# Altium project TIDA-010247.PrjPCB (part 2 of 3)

## Sheet Aux power.SchDoc
size 431 x 279 mm; Date: Not shown in title block; ApprovedBy: Not shown in title block; CheckedBy: Not shown in title block; Author: Not shown in title block; CompanyName: Not shown in title block; Engineer: Not shown in title block; Organization: Not shown in title block; Address1: Not shown in title block; Address2: Not shown in title block; Address3: Not shown in title block; Address4: Not shown in title block; DocumentNumber: 5; Revision: Use project parameter SCH_Rev; SheetNumber: 5; SheetTotal: 7; PageSetup: Record=PageOptions¦CenterHorizontal=True¦CenterVertical=True¦PrintScale=1.00¦XCorrection=1.00¦YCorrection=1.00¦PrintKind=0¦BorderSize=5000000¦LeftOffset=0¦BottomOffset=0¦Orientation=2¦PaperLength=1000¦PaperWidth=1000¦Scale=100¦PaperSource=15¦PrintQuality=600¦MediaType=1¦DitherType=10¦PaperKind=Letter¦PrintScaleMode=1
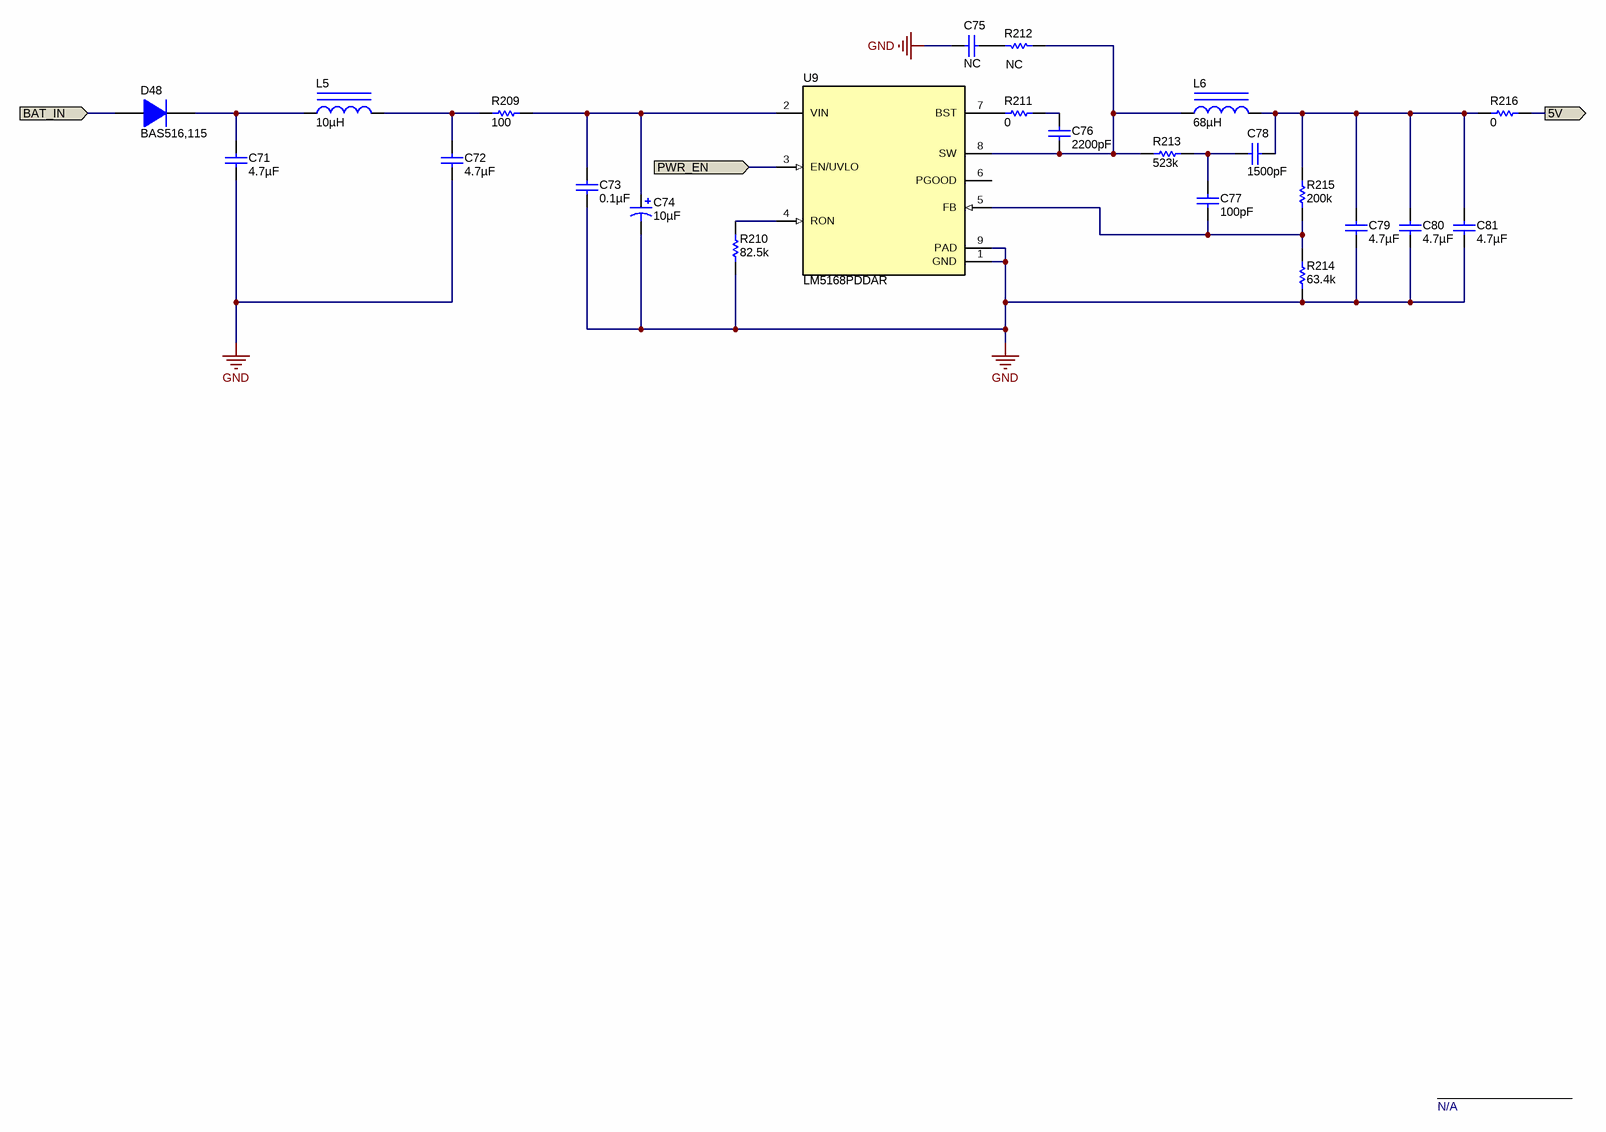
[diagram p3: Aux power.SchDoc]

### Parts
C71  ValueDisplayed: 4.7µF  [1210]  (hidden comment: C3225X7S2A475K200AE)
C72  ValueDisplayed: 4.7µF  [1210]  (hidden comment: C3225X7S2A475K200AE)
C73  ValueDisplayed: 0.1µF  [0603]  (hidden comment: GRM188R72A104KA35D)
C74  ValueDisplayed: 10µF  [UUX_800x620]  (hidden comment: UUX2A100MNL1GS)
C75  ValueDisplayed: NC  [0603]  (hidden comment: GRM1885C1H560JA01D)
C76  ValueDisplayed: 2200pF  [0402]  (hidden comment: GRM155R71H222KA01D)
C77  ValueDisplayed: 100pF  [0603]  (hidden comment: GRM1885C2A101JA01D)
C78  ValueDisplayed: 1500pF  [0402]  (hidden comment: GRM155R71H152KA01D)
C79  ValueDisplayed: 4.7µF  [0805_HV]  (hidden comment: GRM21BR71C475KA73L)
C80  ValueDisplayed: 4.7µF  [0805_HV]  (hidden comment: GRM21BR71C475KA73L)
C81  ValueDisplayed: 4.7µF  [0805_HV]  (hidden comment: GRM21BR71C475KA73L)
D48  BAS516,115  [SOD-523]
L5  ValueDisplayed: 10µH  [WE-MAPI_3015]  (hidden comment: 74438335010)
L6  ValueDisplayed: 68µH  [WE-PD_7345]  (hidden comment: 744777168)
R209  ValueDisplayed: 100  [0603]  (hidden comment: CRCW0603100RFKEA)
R210  ValueDisplayed: 82.5k  [0603]  (hidden comment: CRCW060382K5FKEA)
R211  ValueDisplayed: 0  [0402]  (hidden comment: CRCW04020000Z0ED)
R212  ValueDisplayed: NC  [0603]  (hidden comment: RC0603FR-07499KL)
R213  ValueDisplayed: 523k  [0402]  (hidden comment: RC0402FR-07523KL)
R214  ValueDisplayed: 63.4k  [0603]  (hidden comment: CRCW060363K4FKEA)
R215  ValueDisplayed: 200k  [0603]  (hidden comment: CRCW0603200KFKEA)
R216  ValueDisplayed: 0  [0603]  (hidden comment: CRCW06030000Z0EA)
U9  LM5168PDDAR  [DDA0008E_M]

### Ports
5V (out), BAT_IN (in), PWR_EN (in)

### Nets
GND: C71.2 C72.2 C73.2 C74.2(-) C75.2 C79.2 C80.2 C81.2 R210.1 R214.1 U9.1(GND) U9.9(PAD)
5V: R216.2 ; port 5V
BAT_IN: D48.2(A) ; port BAT_IN
PWR_EN: U9.3(EN/UVLO) ; port PWR_EN
NetC71_1: C71.1 D48.1(K) L5.1
NetC72_1: C72.1 L5.2 R209.1
NetC73_1: C73.1 C74.1(+) R209.2 U9.2(VIN)
NetC75_1: C75.1 R212.1
NetC76_1: C76.1 R211.2
NetC76_2: C76.2 L6.1 R212.2 R213.1 U9.8(SW)
NetC77_1: C77.1 C78.2 R213.2
NetC77_2: C77.2 R214.2 R215.1 U9.5(FB)
NetC78_1: C78.1 C79.1 C80.1 C81.1 L6.2 R215.2 R216.1
NetR210_2: R210.2 U9.4(RON)
NetR211_1: R211.1 U9.7(BST)

Not connected (* = marked no-connect by the designer): U9 6(PGOOD)

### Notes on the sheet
- N/A

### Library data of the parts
C71 C72 = C3225X7S2A475K200AE: CAP, CERM, 4.7 µF, 100 V,+/- 10%, X7S, 1210; Manufacturer: TDK; Polarized: N; CompType: Capacitor; Value: 4.7uF; U/M: EA; Cap_F: 0.0000047; Tolerance_%: 10; VDC_V: 100; Value2: 100V; TaMin_C: -55; TaMax_C: 125; SizeArea_mm2: 8; SizeAreaWB_mm2: 14.7; SizeX_mm: 3.2; SizeY_mm: 2.5; SizeZ_mm: 1.35; AEC Category: Q200; Green_Lifecycle: Active; Green_REACh: Passed
C73 = GRM188R72A104KA35D: CAP, CERM, 0.1 µF, 100 V,+/- 10%, X7R, 0603; Manufacturer: MuRata; Polarized: N; CompType: Capacitor; Value: 0.1uF; U/M: EA; Cap_F: 0.0000001; Tolerance_%: 10; VDC_V: 100; Value2: 100V; TaMin_C: -55; TaMax_C: 125; SizeArea_mm2: 1.28; SizeAreaWB_mm2: 4.68; SizeX_mm: 1.6; SizeY_mm: 0.8; SizeZ_mm: 1; AEC Category: Q200; Green_Lifecycle: Active; Green_REACh: Passed
C74 = UUX2A4R7MCL1GS: CAP, AL, 10 µF, 100 V, +/- 20%, SMD; Manufacturer: Nichicon; Polarized: Y; CompType: Capacitor; Value: 10uF; U/M: EA; Cap_F: 0.0000047; Tolerance_%: 20; VDC_V: 100; Value2: 100V; IRMS_A: 0.042; TaMin_C: -55; TaMax_C: 105; Cap_Case: 8x6.2mm; SizeAreaWB_mm2: 106.09; SizeArea_mm2: 68.89; SizeX_mm: 8.3; SizeZ_mm: 6.5; AEC Category: Q200; AEC Qualified: N
C75 = GRM1885C1H560JA01D: CAP, CERM, 56 pF, 50 V,+/- 5%, C0G/NP0, 0603; Manufacturer: MuRata; Polarized: N; CompType: Capacitor; Value: NC; U/M: EA; Cap_F: 0.000000000056; Tolerance_%: 5; VDC_V: 50; Value2: 50V; TaMin_C: -55; TaMax_C: 125; SizeArea_mm2: 1.28; SizeAreaWB_mm2: 4.68; SizeX_mm: 1.6; SizeY_mm: 0.8; SizeZ_mm: 1; AEC Category: Q200; Green_Lifecycle: Active; Green_REACh: Passed
C76 = GRM155R71H222KA01D: CAP, CERM, 2200 pF, 50 V,+/- 10%, X7R, 0402; Manufacturer: MuRata; Polarized: N; CompType: Capacitor; Value: 2200pF; U/M: EA; Cap_F: 0.0000000022; Tolerance_%: 10; VDC_V: 50; Value2: 50V; TaMin_C: -55; TaMax_C: 125; SizeArea_mm2: 0.5; SizeAreaWB_mm2: 3; SizeX_mm: 1; SizeZ_mm: 0.6; AEC Category: Q200; Green_Lifecycle: Active; Green_REACh: Passed
C77 = GRM1885C2A101JA01D: CAP, CERM, 100 pF, 100 V,+/- 5%, C0G/NP0, 0603; Manufacturer: MuRata; Polarized: N; CompType: Capacitor; Value: 100pF; U/M: EA; Cap_F: 0.0000000001; Tolerance_%: 5; VDC_V: 100; Value2: 100V; TaMin_C: -55; TaMax_C: 125; SizeArea_mm2: 1.28; SizeAreaWB_mm2: 4.68; SizeX_mm: 1.6; SizeY_mm: 0.8; SizeZ_mm: 1; AEC Category: Q200; Green_Lifecycle: Active; Green_REACh: Passed
C78 = GRM155R71H152KA01D: CAP, CERM, 1500 pF, 50 V,+/- 10%, X7R, 0402; Manufacturer: MuRata; Polarized: N; CompType: Capacitor; Value: 1500pF; U/M: EA; Cap_F: 0.0000000015; Tolerance_%: 10; VDC_V: 50; Value2: 50V; TaMin_C: -55; TaMax_C: 125; SizeArea_mm2: 0.5; SizeAreaWB_mm2: 3; SizeX_mm: 1; SizeZ_mm: 0.6; AEC Category: Q200
C79-C81 = GRM21BR71C475KA73L: CAP, CERM, 4.7 µF, 16 V,+/- 10%, X7R, 0805; Manufacturer: MuRata; Polarized: N; CompType: Capacitor; Value: 4.7uF; U/M: EA; Cap_F: 0.0000047; Tolerance_%: 10; ESR_ohm: 0.006; Value1: 0.006 ohm; VDC_V: 16; Value2: 16V; TaMin_C: -55; TaMax_C: 125; Cap_Case: 0805; SizeArea_mm2: 2.5; SizeAreaWB_mm2: 6.75; SizeX_mm: 2; SizeY_mm: 1.25; SizeZ_mm: 1.45; AEC Category: Q200; Green_Lifecycle: Active; Green_REACh: Passed
D48 = BAS516,115: Diode, Switching, 100 V, 0.25 A, SOD-523; Manufacturer: Nexperia; U/M: EA; Vf_V: 1.25; Value: 100V; Value1: 0.25A; Value2: 1.25V; Io_A: 0.25; Vr_V: 100; TJmax_C: 150; SizeAreaWB_mm2: 5.13; SizeArea_mm2: 1.53; SizeX_mm: 1.7; SizeY_mm: 0.9; SizeZ_mm: 0.65; AEC Category: Q101; Green_Lifecycle: Not Set; Green_REACh: Incomplete
L5 = 74438335010: Inductor, Shielded, 1 µH, 2.7 A, 0.039 ohm, SMD; Manufacturer: Wurth Elektronik; Value: 1uH; Ind_H: 1.0E-6; Imax_A: 2.7; Irms: 2.7A @ 40C rise; Isat: 4.5A @ 20% inductance drop; DCR_ohm: 0.039; Value2: 2.7A; SizeAreaWB_mm2: 16; SizeArea_mm2: 9; SizeX_mm: 3; SizeZ_mm: 1.2; AEC Category: Q200; Green_Lifecycle: Active; Green_REACh: Passed
L6 = 744777168: Inductor, Shielded Drum Core, Metal Composite, 68 µH, 0.87 A, 0.239 ohm, SMD; Manufacturer: Wurth Elektronik; Value: 68uH; Ind_H: 68.0E-6; Imax_A: 0.87; Irms: 0.87A @ 40C rise; Isat: 0.95A @ 10% inductance drop; DCR_ohm: 0.239; Value2: 0.87A; SizeAreaWB_mm2: 86.49; SizeArea_mm2: 53.29; SizeX_mm: 7.3; SizeZ_mm: 4.5; AEC Category: Q200; Green_Lifecycle: Active; Green_REACh: Passed
R209 = CRCW0603100RFKEA: RES, 100, 1%, 0.1 W, 0603; Manufacturer: Vishay-Dale; CompType: Resistor; Value: 100; Value_Code: 100R; Tolerance_%: 1; Power_W: 0.1; Value2: 0.1W; VDC_V: 75; TempCo: 100 ppm/C; SizeArea_mm2: 1.28; SizeX_mm: 1.6; SizeY_mm: 0.8; EIA_Code: E96; U/M: EA; AEC Category: Q200; Green_Lifecycle: Active; Green_REACh: Passed
R210 = CRCW060382K5FKEA: RES, 82.5 k, 1%, 0.1 W, 0603; Manufacturer: Vishay-Dale; CompType: Resistor; Value: 82.5k; Res_ohm: 82500; Value_Code: 82k5; Tolerance_%: 1; Power_W: 0.1; Value2: 0.1W; VDC_V: 75; TempCo: 100 ppm/C; SizeArea_mm2: 1.28; SizeX_mm: 1.6; SizeY_mm: 0.8; EIA_Code: E96; U/M: EA; AEC Category: Q200; Green_Lifecycle: Active; Green_REACh: Passed
R211 = CRCW04020000Z0ED: RES, 0, 5%, 0.063 W, 0402; Manufacturer: Vishay-Dale; CompType: Resistor; Value: 0; Value_Code: 0000; Tolerance_%: 5; Power_W: 0.063; Value2: 0.063W; VDC_V: 50; TempCo: 200 ppm/C; SizeArea_mm2: 0.5; SizeX_mm: 1; SizeZ_mm: 0.6; EIA_Code: E24; U/M: EA; AEC Category: Q200; Green_Lifecycle: Active; Green_REACh: Passed
R212 = RC0603FR-07499KL: RES, 499 k, 1%, 0.1 W, 0603; Manufacturer: Yageo America; CompType: Resistor; Value: NC; Res_ohm: 499000; Value_Code: 499k; Tolerance_%: 1; Power_W: 0.1; Value2: 0.1W; VDC_V: 150; TempCo: 200 ppm/C; SizeArea_mm2: 1.28; SizeX_mm: 1.6; SizeY_mm: 0.8; EIA_Code: E96; U/M: EA; AEC Category: Q200; Green_Lifecycle: Active; Green_REACh: Passed
R213 = CRCW0402523KFKED: RES, 523 k, 1%, 0.063 W, 0402; Manufacturer: Yageo; CompType: Resistor; Value: 523k; Res_ohm: 523000; Tolerance_%: 1; Power_W: 0.063; Value2: 0.063W; VDC_V: 50; TempCo: 100 ppm/C; SizeArea_mm2: 0.5; SizeZ_mm: 0.6; EIA_Code: E96; U/M: EA; AEC Category: Q200
R214 = CRCW060363K4FKEA: RES, 63.4 k, 1%, 0.1 W, 0603; Manufacturer: Vishay-Dale; CompType: Resistor; Value: 63.4k; Res_ohm: 63400; Value_Code: 63k4; Tolerance_%: 1; Power_W: 0.1; Value2: 0.1W; VDC_V: 75; TempCo: 100 ppm/C; SizeArea_mm2: 1.28; SizeX_mm: 1.6; SizeY_mm: 0.8; EIA_Code: E96; U/M: EA; AEC Category: Q200
R215 = CRCW0603200KFKEA: RES, 200 k, 1%, 0.1 W, 0603; Manufacturer: Vishay-Dale; CompType: Resistor; Value: 200k; Res_ohm: 200000; Tolerance_%: 1; Power_W: 0.1; Value2: 0.1W; VDC_V: 75; TempCo: 100 ppm/C; SizeArea_mm2: 1.28; SizeX_mm: 1.6; SizeY_mm: 0.8; EIA_Code: E96; U/M: EA; AEC Category: Q200; Green_Lifecycle: Active; Green_REACh: Passed
R216 = CRCW06030000Z0EA: RES, 0, 5%, 0.1 W, 0603; Manufacturer: Vishay-Dale; CompType: Resistor; Value: 0; Value_Code: 0000; Tolerance_%: 5; Power_W: 0.1; Value2: 0.1W; VDC_V: 75; TempCo: 200 ppm/C; SizeArea_mm2: 1.28; SizeX_mm: 1.6; SizeY_mm: 0.8; SizeZ_mm: 1; EIA_Code: E24; U/M: EA; AEC Category: Q200; Green_Lifecycle: Active; Green_REACh: Passed
U9 = CMP-0861029-1: 0.3-A,120-V, Step-Down Converter with Fly-buck Capability; Alternate Manufacturer: Texas Instruments; SizeAreaWB_mm2: 55.2; SizeZ_mm: 1.7; SizeX_mm: 6; AEC Qualified: N; AEC Category: Q200; SizeArea_mm2: 29.4; CompType: IC; SizeY_mm: 4.9

## Sheet MCU and Communication.SchDoc
size 431 x 279 mm; Date: Not shown in title block; ApprovedBy: Not shown in title block; CheckedBy: Not shown in title block; Author: Not shown in title block; CompanyName: Not shown in title block; Engineer: Not shown in title block; Organization: Not shown in title block; Address1: Not shown in title block; Address2: Not shown in title block; Address3: Not shown in title block; Address4: Not shown in title block; DocumentNumber: 3; Revision: Use project parameter SCH_Rev; SheetNumber: 3; SheetTotal: 7; PageSetup: Record=PageOptions¦CenterHorizontal=True¦CenterVertical=True¦PrintScale=1.00¦XCorrection=1.00¦YCorrection=1.00¦PrintKind=0¦BorderSize=5000000¦LeftOffset=0¦BottomOffset=0¦Orientation=2¦PaperLength=1000¦PaperWidth=1000¦Scale=100¦PaperSource=15¦PrintQuality=600¦MediaType=1¦DitherType=10¦PaperKind=Letter¦PrintScaleMode=1
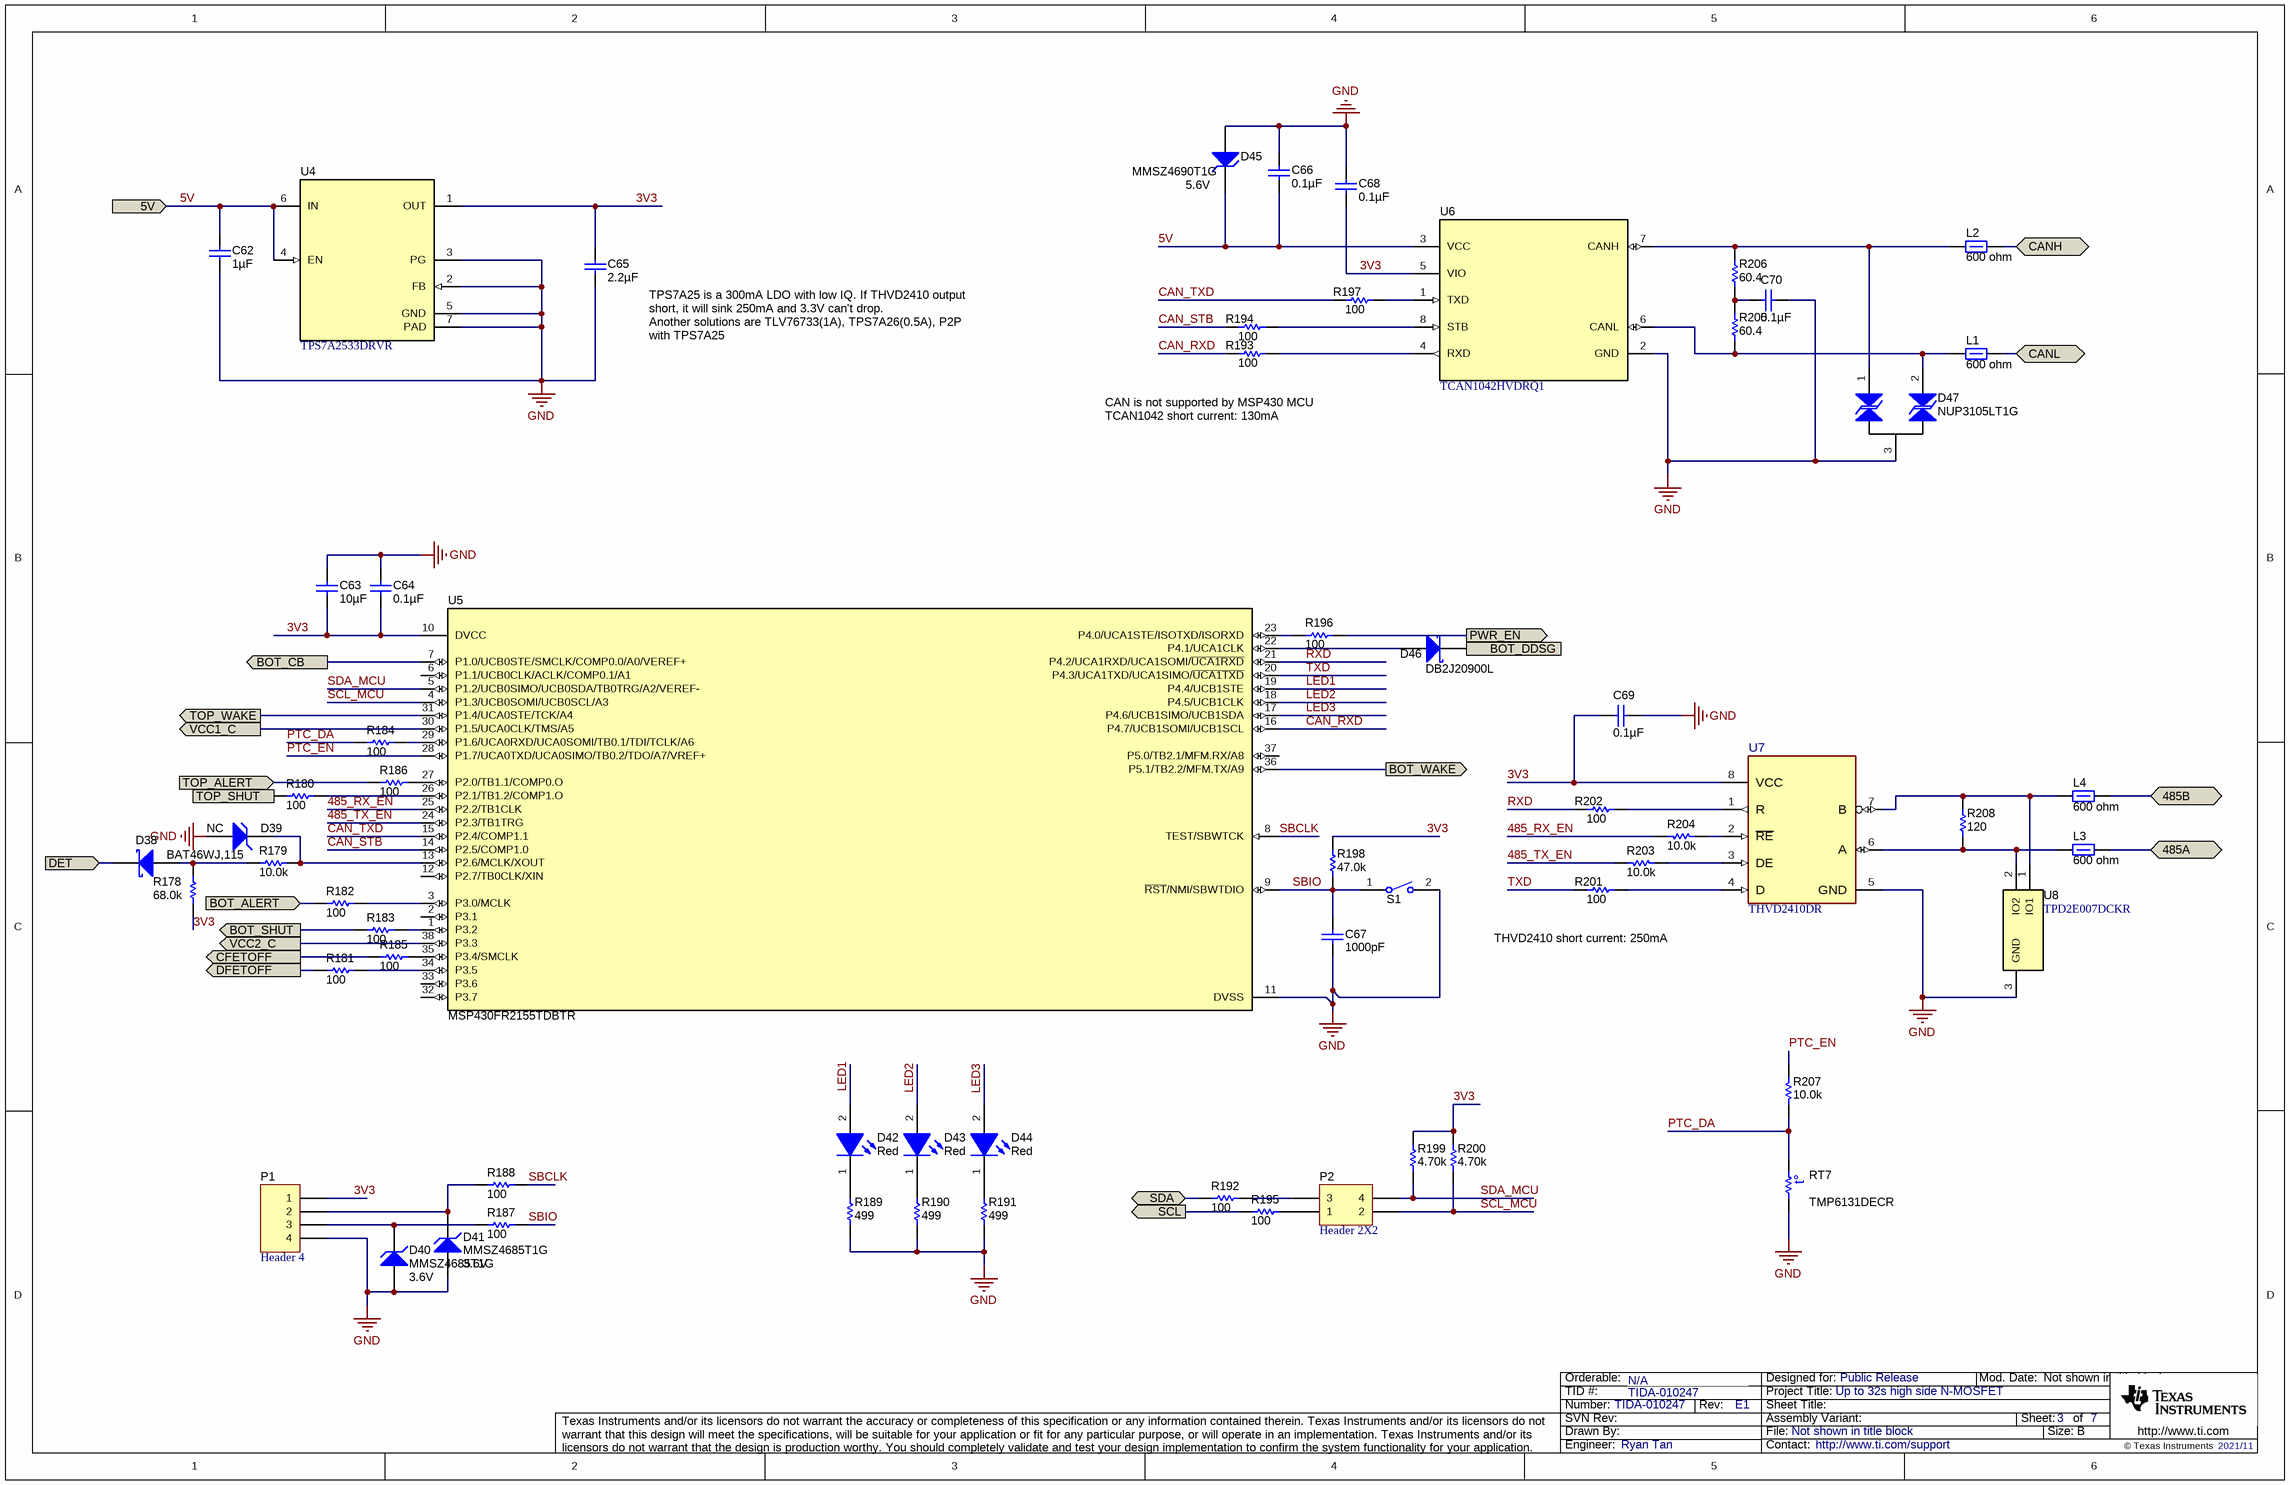
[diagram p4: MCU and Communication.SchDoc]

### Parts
C62  ValueDisplayed: 1µF  [0603]  (hidden comment: GCM188R71C105KA64D)
C63  ValueDisplayed: 10µF  [0805_HV]  (hidden comment: C2012X6S1C106K085AC)
C64  ValueDisplayed: 0.1µF  [0603]  (hidden comment: GRM188R71H104KA93D)
C65  ValueDisplayed: 2.2µF  [0603]  (hidden comment: EMK107BB7225MA-T)
C66  ValueDisplayed: 0.1µF  [0603]  (hidden comment: GRM188R71H104KA93D)
C67  ValueDisplayed: 1000pF  [0603]  (hidden comment: GRM1885C1H102JA01D)
C68  ValueDisplayed: 0.1µF  [0603]  (hidden comment: GRM188R71H104KA93D)
C69  ValueDisplayed: 0.1µF  [0603]  (hidden comment: GRM188R71H104KA93D)
C70  ValueDisplayed: 0.1µF  [0603]  (hidden comment: GRM188R71H104KA93D)
D38  BAT46WJ,115  [SOD-323F]
D39  value NC  [SOD-123]  (hidden comment: MMSZ4685T1G)
D40  MMSZ4685T1G  value 3.6V  [SOD-123]
D41  MMSZ4685T1G  value 3.6V  [SOD-123]
D42  value Red  [WL-SMCW_RED]  (hidden comment: 150060RS75000)
D43  value Red  [WL-SMCW_RED]  (hidden comment: 150060RS75000)
D44  value Red  [WL-SMCW_RED]  (hidden comment: 150060RS75000)
D45  MMSZ4690T1G  value 5.6V  [SOD-123]
D46  DB2J20900L  [SOD-323F]
D47  NUP3105LT1G  [SOT-23]
L1  ValueDisplayed: 600 ohm  [0603]  (hidden comment: 74279265)
L2  ValueDisplayed: 600 ohm  [0603]  (hidden comment: 74279265)
L3  ValueDisplayed: 600 ohm  [0603]  (hidden comment: 74279265)
L4  ValueDisplayed: 600 ohm  [0603]  (hidden comment: 74279265)
P1  Header 4  [HDR1X4]
P2  Header 2X2  [HDR2X2]
R178  ValueDisplayed: 68.0k  [0603]  (hidden comment: RC0603FR-0768KL)
R179  ValueDisplayed: 10.0k  [0603]  (hidden comment: CRCW060310K0FKEA)
R180  ValueDisplayed: 100  [0603]  (hidden comment: CRCW0603100RFKEA)
R181  ValueDisplayed: 100  [0603]  (hidden comment: CRCW0603100RFKEA)
R182  ValueDisplayed: 100  [0603]  (hidden comment: CRCW0603100RFKEA)
R183  ValueDisplayed: 100  [0603]  (hidden comment: CRCW0603100RFKEA)
R184  ValueDisplayed: 100  [0603]  (hidden comment: CRCW0603100RFKEA)
R185  ValueDisplayed: 100  [0603]  (hidden comment: CRCW0603100RFKEA)
R186  ValueDisplayed: 100  [0603]  (hidden comment: CRCW0603100RFKEA)
R187  ValueDisplayed: 100  [0603]  (hidden comment: CRCW0603100RFKEA)
R188  ValueDisplayed: 100  [0603]  (hidden comment: CRCW0603100RFKEA)
R189  ValueDisplayed: 499  [0603]  (hidden comment: RC0603FR-07499RL)
R190  ValueDisplayed: 499  [0603]  (hidden comment: RC0603FR-07499RL)
R191  ValueDisplayed: 499  [0603]  (hidden comment: RC0603FR-07499RL)
R192  ValueDisplayed: 100  [0603]  (hidden comment: CRCW0603100RFKEA)
R193  ValueDisplayed: 100  [0603]  (hidden comment: CRCW0603100RFKEA)
R194  ValueDisplayed: 100  [0603]  (hidden comment: CRCW0603100RFKEA)
R195  ValueDisplayed: 100  [0603]  (hidden comment: CRCW0603100RFKEA)
R196  ValueDisplayed: 100  [0603]  (hidden comment: CRCW0603100RFKEA)
R197  ValueDisplayed: 100  [0603]  (hidden comment: CRCW0603100RFKEA)
R198  ValueDisplayed: 47.0k  [0603]  (hidden comment: RC0603FR-0747KL)
R199  ValueDisplayed: 4.70k  [0603]  (hidden comment: RC0603FR-074K7L)
R200  ValueDisplayed: 4.70k  [0603]  (hidden comment: RC0603FR-074K7L)
R201  ValueDisplayed: 100  [0603]  (hidden comment: CRCW0603100RFKEA)
R202  ValueDisplayed: 100  [0603]  (hidden comment: CRCW0603100RFKEA)
R203  ValueDisplayed: 10.0k  [0603]  (hidden comment: CRCW060310K0FKEA)
R204  ValueDisplayed: 10.0k  [0603]  (hidden comment: CRCW060310K0FKEA)
R205  ValueDisplayed: 60.4  [0603]  (hidden comment: RC0603FR-0760R4L)
R206  ValueDisplayed: 60.4  [0603]  (hidden comment: RC0603FR-0760R4L)
R207  ValueDisplayed: 10.0k  [0603]  (hidden comment: CRCW060310K0FKEA)
R208  ValueDisplayed: 120  [0603]  (hidden comment: RC0603FR-07120RL)
RT7  TMP6131DECR  [DEC0002A]
S1  RS-032G05A3-SM RT  [SW_RS-032G05A3-SM]  (value not drawn)
U4  PartNumber: TPS7A2533DRVR  [DRV0006A]  (hidden comment: TPS7A2501DRVR)
U5  MSP430FR2155TDBTR  [DBT0038A_N]
U6  TCAN1042HVDRQ1  [D0008A_L]
U7  PartNumber: THVD2410DR  [D0008B-MFG]  (hidden comment: THVD1400D)
U8  TPD2E007DCKR  [DCK0003A_N]

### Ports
5V (in), 485A (bidir), 485B (bidir), BOT_ALERT (in), BOT_CB (out), BOT_DDSG (out), BOT_SHUT (out), BOT_WAKE (out), CANH (bidir), CANL (bidir), CFETOFF (out), DET (in), DFETOFF (out), PWR_EN (out), SCL (out), SDA (bidir), TOP_ALERT (in), TOP_SHUT (out), TOP_WAKE (out), VCC1_C (out), VCC2_C (out)

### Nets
GND: C62.2 C63.1 C64.1 C65.2 C66.2 C67.2 C68.2 C69.2 C70.1 D39.2(A) D40.2(A) D41.2(A) D45.2(A) D47.3 P1.4 R189.1 R190.1 R191.1 RT7.1 S1.2 U4.2(FB) U4.3(PG) U4.5(GND) U4.7(PAD) U5.11(DVSS) U6.2(GND) U7.5(GND) U8.3(GND)
3V3: C63.2 C64.2 C65.1 C68.1 C69.1 P1.1 R178.2 R198.2 R199.2 R200.2 U4.1(OUT) U5.10(DVCC) U6.5(VIO) U7.8(VCC)
5V: C62.1 C66.1 D45.1(K) U4.4(EN) U4.6(IN) U6.3(VCC) ; port 5V
485_RX_EN: R204.1 U5.25(P2.2/TB1CLK)
485_TX_EN: R203.1 U5.24(P2.3/TB1TRG)
485A: L3.1 ; port 485A
485B: L4.1 ; port 485B
BOT_ALERT: R182.2 ; port BOT_ALERT
BOT_CB: U5.7(P1.0/UCB0STE/SMCLK/COMP0.0/A0/VEREF+) ; port BOT_CB
BOT_DDSG: D46.1(K) ; port BOT_DDSG
BOT_SHUT: R183.1 ; port BOT_SHUT
BOT_WAKE: U5.36(P5.1/TB2.2/MFM.TX/A9) ; port BOT_WAKE
CAN_RXD: R193.2 U5.16(P4.7/UCB1SOMI/UCB1SCL)
CAN_STB: R194.2 U5.14(P2.5/COMP1.0)
CAN_TXD: R197.2 U5.15(P2.4/COMP1.1)
CANH: L2.1 ; port CANH
CANL: L1.1 ; port CANL
CFETOFF: R185.2 ; port CFETOFF
DET: D38.1(K) ; port DET
DFETOFF: R181.2 ; port DFETOFF
LED1: D42.2(A) U5.19(P4.4/UCB1STE)
LED2: D43.2(A) U5.18(P4.5/UCB1CLK)
LED3: D44.2(A) U5.17(P4.6/UCB1SIMO/UCB1SDA)
PTC_DA: R184.2 R207.1 RT7.2
PTC_EN: R207.2 U5.28(P1.7/UCA0TXD/UCA0SIMO/TB0.2/TDO/A7/VREF+)
PWR_EN: R196.1 ; port PWR_EN
RXD: R202.2 U5.21(P4.2/UCA1RXD/UCA1SOMI/~{UCA1RXD})
SBCLK: R188.1 U5.8(TEST/SBWTCK)
SBIO: C67.1 R187.1 R198.1 S1.1 U5.9(~{RST}/NMI/SBWTDIO)
SCL: R195.1 ; port SCL
SCL_MCU: P2.2 R200.1 U5.4(P1.3/UCB0SOMI/UCB0SCL/A3)
SDA: R192.1 ; port SDA
SDA_MCU: P2.4 R199.1 U5.5(P1.2/UCB0SIMO/UCB0SDA/TB0TRG/A2/VEREF-)
TOP_ALERT: R186.2 ; port TOP_ALERT
TOP_SHUT: R180.1 ; port TOP_SHUT
TOP_WAKE: U5.31(P1.4/UCA0STE/TCK/A4) ; port TOP_WAKE
TXD: R201.2 U5.20(P4.3/UCA1TXD/UCA1SIMO/~{UCA1TXD})
VCC1_C: U5.30(P1.5/UCA0CLK/TMS/A5) ; port VCC1_C
VCC2_C: U5.38(P3.3) ; port VCC2_C
NetC70_2: C70.2 R205.1 R206.2
NetD38_2: D38.2(A) R178.1 R179.2
NetD39_1: D39.1(K) R179.1 U5.13(P2.6/MCLK/XOUT)
NetD40_1: D40.1(K) P1.3 R187.2
NetD41_1: D41.1(K) P1.2 R188.2
NetD42_1: D42.1(K) R189.2
NetD43_1: D43.1(K) R190.2
NetD44_1: D44.1(K) R191.2
NetD46_2: D46.2(A) U5.22(P4.1/UCA1CLK)
NetD47_1: D47.1 L2.2 R206.1 U6.7(CANH)
NetD47_2: D47.2 L1.2 R205.2 U6.6(CANL)
NetL3_2: L3.2 R208.1 U7.6(A) U8.2(IO2)
NetL4_2: L4.2 R208.2 U7.7(B) U8.1(IO1)
NetP2_1: P2.1 R195.2
NetP2_3: P2.3 R192.2
NetR180_2: R180.2 U5.26(P2.1/TB1.2/COMP1.O)
NetR181_1: R181.1 U5.34(P3.5)
NetR182_1: R182.1 U5.3(P3.0/MCLK)
NetR183_2: R183.2 U5.1(P3.2)
NetR184_1: R184.1 U5.29(P1.6/UCA0RXD/UCA0SOMI/TB0.1/TDI/TCLK/A6)
NetR185_1: R185.1 U5.35(P3.4/SMCLK)
NetR186_1: R186.1 U5.27(P2.0/TB1.1/COMP0.O)
NetR193_1: R193.1 U6.4(RXD)
NetR194_1: R194.1 U6.8(STB)
NetR196_2: R196.2 U5.23(P4.0/UCA1STE/ISOTXD/ISORXD)
NetR197_1: R197.1 U6.1(TXD)
NetR201_1: R201.1 U7.4(D)
NetR202_1: R202.1 U7.1(R)
NetR203_2: R203.2 U7.3(DE)
NetR204_2: R204.2 U7.2(~{RE})

Not connected (* = marked no-connect by the designer): U5 2(P3.1) 6(P1.1/UCB0CLK/ACLK/COMP0.1/A1) 12(P2.7/TB0CLK/XIN) 32(P3.7) 33(P3.6) 37(P5.0/TB2.1/MFM.RX/A8)

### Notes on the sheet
- TPS7A25 is a 300mA LDO with low IQ. If THVD2410 output short, it will sink 250mA and 3.3V can't drop.
  Another solutions are TLV76733(1A), TPS7A26(0.5A), P2P with TPS7A25
- (near R193) CAN is not supported by MSP430 MCU
  TCAN1042 short current: 130mA
- (near R201) THVD2410 short current: 250mA
- N/A

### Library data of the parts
C62 = GCM188R71C105KA64D: CAP, CERM, 1 µF, 16 V,+/- 10%, X7R, AEC-Q200 Grade 1, 0603; Manufacturer: MuRata; Polarized: N; CompType: Capacitor; Value: 1uF; U/M: EA; Cap_F: 0.000001; Tolerance_%: 10; VDC_V: 16; Value2: 16V; TaMin_C: -55; TaMax_C: 125; SizeArea_mm2: 1.28; SizeAreaWB_mm2: 4.68; SizeX_mm: 1.6; SizeY_mm: 0.8; SizeZ_mm: 1; AEC Category: Q200; AEC Qualified: Y; Green_Lifecycle: Active; Green_REACh: Passed
C63 = C2012X6S1C106K085AC: CAP, CERM, 10 µF, 16 V,+/- 10%, X6S, 0805; Manufacturer: TDK; Polarized: N; CompType: Capacitor; Value: 10uF; U/M: EA; Cap_F: 0.00001; Tolerance_%: 10; ESR_ohm: 0.002818; Value1: 0.002818 ohm; VDC_V: 16; Value2: 16V; IRMS_A: 3.88676; TaMin_C: -55; TaMax_C: 105; Cap_Case: 0805; SizeArea_mm2: 2.5; SizeAreaWB_mm2: 6.75; SizeX_mm: 2; SizeY_mm: 1.25; SizeZ_mm: 1.45; AEC Category: Q200
C64 C66 C68-C70 = GRM188R71H104KA93D: CAP, CERM, 0.1 µF, 50 V,+/- 10%, X7R, 0603; Manufacturer: MuRata; Polarized: N; CompType: Capacitor; Value: 0.1uF; U/M: EA; Cap_F: 0.0000001; Tolerance_%: 10; VDC_V: 50; Value2: 50V; TaMin_C: -55; TaMax_C: 125; SizeArea_mm2: 1.28; SizeAreaWB_mm2: 4.68; SizeX_mm: 1.6; SizeY_mm: 0.8; SizeZ_mm: 1; AEC Category: Q200; Green_Lifecycle: Active; Green_REACh: Passed
C65 = EMK107BB7225MA-T: CAP, CERM, 2.2 µF, 16 V,+/- 10%, X7R, 0603; Manufacturer: Taiyo Yuden; Polarized: N; CompType: Capacitor; Value: 2.2uF; U/M: EA; Cap_F: 0.0000022; Tolerance_%: 10; VDC_V: 16; Value2: 16V; TaMin_C: -55; TaMax_C: 125; SizeArea_mm2: 1.28; SizeAreaWB_mm2: 4.68; SizeX_mm: 1.6; SizeY_mm: 0.8; SizeZ_mm: 1; AEC Category: Q200
C67 = GRM1885C1H102JA01D: CAP, CERM, 1000 pF, 50 V,+/- 5%, C0G/NP0, 0603; Manufacturer: MuRata; Polarized: N; CompType: Capacitor; Value: 1000pF; U/M: EA; Cap_F: 0.000000001; Tolerance_%: 5; VDC_V: 50; Value2: 50V; TaMin_C: -55; TaMax_C: 125; SizeArea_mm2: 1.28; SizeAreaWB_mm2: 4.68; SizeX_mm: 1.6; SizeY_mm: 0.8; SizeZ_mm: 1; AEC Category: Q200; Green_Lifecycle: Active; Green_REACh: Passed
D38 = BAT46WJ,115: Diode, Schottky, 100 V, 0.25 A, SOD-323F; Manufacturer: Nexperia; U/M: EA; Vf_V: 0.85; Value: 100V; Value1: 0.25A; Value2: 0.85V; Io_A: 0.25; Vr_V: 100; TJmax_C: 150; SizeAreaWB_mm2: 7.875; SizeArea_mm2: 3.125; SizeX_mm: 2.5; SizeY_mm: 1.25; SizeZ_mm: 0.8; AEC Category: Q101; Green_Lifecycle: Not Set; Green_REACh: Incomplete
D39-D41 = MMSZ4685T1G: Diode, Zener, 3.6 V, 500 mW, SOD-123; Manufacturer: ON Semiconductor; SymbolCreator: a0412235; U/M: EA; Power_W: 0.5; Vz_V: 3.6; Value1: 0.5W; RJA_CperW: 340; SizeAreaWB_mm2: 13.095; SizeArea_mm2: 6.545; SizeX_mm: 3.85; SizeY_mm: 1.7; SizeZ_mm: 1.35; AEC Category: Q101; Green_Lifecycle: Active; Green_REACh: Passed
D42-D44 = 150060RS75000: LED, Red, SMD; Manufacturer: Wurth Elektronik; Type: AlInGaP; Vf_V: 2; Value2: 2V; Io_A: 0.03; Vr_V: 5; Tjmax_C: 85; Power_TotalModule: 0.072; Value1: 0.072W; Angle: 140; U/M: EA; Green_Lifecycle: Active; Green_REACh: Passed
D45 = MMSZ4690T1G: Diode, Zener, 5.6 V, 500 mW, SOD-123; Manufacturer: ON Semiconductor; SymbolCreator: a0412235; U/M: EA; Power_W: 0.5; Vz_V: 5.6; Value1: 0.5W; RJA_CperW: 340; SizeAreaWB_mm2: 13.095; SizeArea_mm2: 6.545; SizeX_mm: 3.85; SizeY_mm: 1.7; SizeZ_mm: 1.35; AEC Category: Q101; Green_Lifecycle: Active; Green_REACh: Passed
D46 = DB2J20900L: Diode, Schottky, 20 V, 0.5 A, SOD-323F; Manufacturer: Panasonic; U/M: EA; Vf_V: 0.5; Value: 20V; Value1: 0.5A; Value2: 0.5V; Vr_V: 20; TJmax_C: 125; SizeAreaWB_mm2: 7.875; SizeArea_mm2: 3.125; SizeX_mm: 2.5; SizeY_mm: 1.25; SizeZ_mm: 0.8; AEC Category: Q101; AEC Qualified: N; Green_Lifecycle: Not Set; Green_REACh: Incomplete
D47 = NUP2105LT1G: Diode, TVS, Bi, 24 V, SOT-23; Manufacturer: ON Semiconductor; SymbolCreator: a0411947; Value: 24V; U/M: EA; Power_W: 0.35; Vr_V: 24; Value1: 0.35W; SizeAreaWB_mm2: 14; SizeArea_mm2: 7.5; SizeX_mm: 2.5; SizeY_mm: 3; SizeZ_mm: 1.1; AEC Category: Q101
L1-L4 = 74279265: Ferrite Bead, 600 ohm @ 100 MHz, 0.2 A, 0603; Manufacturer: Wurth Elektronik; Value: 600 ohm; Imax_A: 0.2; DCR_ohm: 0.45; Value1: 0.45 ohm; Value2: 0.2A; SizeAreaWB_mm2: 4.68; SizeArea_mm2: 1.28; SizeX_mm: 1.6; SizeY_mm: 0.8; SizeZ_mm: 1; ZTyp@100MHz_Ohm: 600; Ztyp@1GHz_Ohm: 223.805; Green_Lifecycle: Active; Green_REACh: Passed
P1 = Header 4: Header, 4-Pin
P2 = Header 2X2: Header, 2-Pin, Dual row
R178 = RC0603FR-0768KL: RES, 68.0 k, 1%, 0.1 W, 0603; Manufacturer: Yageo America; CompType: Resistor; Value: 68.0k; Res_ohm: 68000; Value_Code: 68k0; Tolerance_%: 1; Power_W: 0.1; Value2: 0.1W; VDC_V: 150; TempCo: 200 ppm/C; SizeArea_mm2: 1.28; SizeX_mm: 1.6; SizeY_mm: 0.8; U/M: EA; AEC Category: Q200; Green_Lifecycle: Active; Green_REACh: Passed
R179 R203 R204 R207 = CRCW060310K0FKEA: RES, 10.0 k, 1%, 0.1 W, 0603; Manufacturer: Vishay-Dale; CompType: Resistor; Value: 10.0k; Res_ohm: 10000; Value_Code: 10k0; Tolerance_%: 1; Power_W: 0.1; Value2: 0.1W; VDC_V: 75; TempCo: 100 ppm/C; SizeArea_mm2: 1.28; SizeX_mm: 1.6; SizeY_mm: 0.8; EIA_Code: E96; U/M: EA; AEC Category: Q200; Green_Lifecycle: Active; Green_REACh: Passed
R180-R188 R192-R197 R201 R202 = CRCW0603100RFKEA: as R209 on sheet Aux power
R189-R191 = RC0603FR-07499RL: RES, 499, 1%, 0.1 W, 0603; Manufacturer: Yageo America; CompType: Resistor; Value: 499; Value_Code: 499R; Tolerance_%: 1; Power_W: 0.1; Value2: 0.1W; VDC_V: 150; TempCo: 200 ppm/C; SizeArea_mm2: 1.28; SizeX_mm: 1.6; SizeY_mm: 0.8; EIA_Code: E96; U/M: EA; AEC Category: Q200; Green_Lifecycle: Active; Green_REACh: Passed
R198 = RC0603FR-0747KL: RES, 47.0 k, 1%, 0.1 W, 0603; Manufacturer: Yageo America; CompType: Resistor; Value: 47.0k; Res_ohm: 47000; Value_Code: 47k0; Tolerance_%: 1; Power_W: 0.1; Value2: 0.1W; VDC_V: 150; TempCo: 200 ppm/C; SizeArea_mm2: 1.28; SizeX_mm: 1.6; SizeY_mm: 0.8; U/M: EA; AEC Category: Q200; Green_Lifecycle: Active; Green_REACh: Passed
R199 R200 = RC0603FR-074K7L: RES, 4.70 k, 1%, 0.1 W, 0603; Manufacturer: Yageo America; CompType: Resistor; Value: 4.70k; Res_ohm: 4700; Value_Code: 4k70; Tolerance_%: 1; Power_W: 0.1; Value2: 0.1W; VDC_V: 150; TempCo: 200 ppm/C; SizeArea_mm2: 1.28; SizeX_mm: 1.6; SizeY_mm: 0.8; U/M: EA; AEC Category: Q200; Green_Lifecycle: Active; Green_REACh: Passed
R205 R206 = RC0603FR-0760R4L: RES, 60.4, 1%, 0.1 W, 0603; Manufacturer: Yageo America; CompType: Resistor; Value: 60.4; Value_Code: 60R4; Tolerance_%: 1; Power_W: 0.1; Value2: 0.1W; VDC_V: 150; TempCo: 200 ppm/C; SizeArea_mm2: 1.28; SizeX_mm: 1.6; SizeY_mm: 0.8; EIA_Code: E96; U/M: EA; AEC Category: Q200
R208 = RC0603FR-07120RL: RES, 120, 1%, 0.1 W, 0603; Manufacturer: Yageo America; CompType: Resistor; Value: 120; Value_Code: 120R; Tolerance_%: 1; Power_W: 0.1; Value2: 0.1W; VDC_V: 150; TempCo: 200 ppm/C; SizeArea_mm2: 1.28; SizeX_mm: 1.6; SizeY_mm: 0.8; U/M: EA; AEC Category: Q200; Green_Lifecycle: Active; Green_REACh: Passed
RT7 = CMP-0084566-1: Thermistor, DEC0002A (X1SON-2); Alternate Manufacturer: Texas Instruments; Alternate PartNumber: TMP6131DECT; CompType: IC; AEC Category: Q200; SizeX_mm: 1; AEC Qualified: N; SizeZ_mm: 0.5; SizeArea_mm2: 0.6; SizeAreaWB_mm2: 3.2
S1 = RS-032G05A3-SM RT: Switch, Tactile, SPST-NO, 0.05A, 12V, SMD; Manufacturer: C&K Components; SymbolCreator: a0799628; VDC_V: 12; SwitchFunction: Off-Mom; PositionCount: 1; CurrentRating_mA: 50; Green_Lifecycle: Not Set; Green_REACh: Incomplete
U4 = CMP-0078340-1: 300-mA, 18-V, Low IQ, Low Dropout Voltage Regulator with Power Good, DRV0006A (WSON-6); Manufacturer: Texas Instruments; SizeZ_mm: 0.8; SizeX_mm: 2; AEC Category: Q200; AEC Qualified: N; SizeArea_mm2: 4; CompType: IC; SizeAreaWB_mm2: 9
U5 = CMP-0084060-1: 24MHz 105C ULP Microcontroller With 32 KB FRAM, 4 KB SRAM, 44 IO, 12-bit ADC, DBT0038A (TSSOP-38); Manufacturer: Texas Instruments; Rating: Catalog; SizeAreaWB_mm2: 98.28; SizeArea_mm2: 62.08; AEC Qualified: N; AEC Category: Q200; SizeZ_mm: 1.2; SizeY_mm: 9.7; CompType: IC; SizeX_mm: 6.4
U6 = CMP-0075993-1: Automotive Fault Protected CAN Transceiver With Flexible Data-Rate, D0008A (SOIC-8); Manufacturer: Texas Instruments; Alternate PartNumber: TCAN1042HVDQ1; SizeAreaWB_mm2: 56.58; SizeArea_mm2: 30.38; SizeZ_mm: 1.75; SizeY_mm: 6.2; U/M: EA; CompType: IC; SizeX_mm: 4.9
U7 = CMP-0089978-1: 500 kbps RS-485 Transceivers With ±8-kV IEC ESD Protection; Manufacturer: Texas Instruments; Interface: RS-485,RS-422; SizeZ_mm: 1.75mm; Number Of Receivers: 1; TaMax_C: +125°C; TJmax_C: +150°C; Min Supply Voltage: 4.5V; Nominal Supply Current: 275-440uA; Simplex Duplex: Half-Duplex; Standoff Height: 0.11mm; Max Supply Voltage: 5.5V; TaMin_C: -40°C; Data Rate: 500kbits/s; AEC Qualified: No
U8 = TPD2E007DCKR: ESD Protection Array for AC Signal Data Interface, 2 Channels, -40 to +85 degC, 3-pin SC70 (DCK), Green (RoHS & no Sb/Br); Manufacturer: Texas Instruments; Alternate PartNumber: Equivalent; Breakdown Voltage(Min)(V): +/-14; IEC 61000-4-2 Air-Gap(+/- kV): 15; IEC 61000-4-2 Contact(+/- kV): 8; IO Leakage Current(nA): 50; SubFamily: ESD Solution

## Sheet High-side MOSFETs and driver.SchDoc
size 431 x 279 mm; Date: Not shown in title block; ApprovedBy: Not shown in title block; CheckedBy: Not shown in title block; Author: Not shown in title block; CompanyName: Not shown in title block; Engineer: Not shown in title block; Organization: Not shown in title block; Address1: Not shown in title block; Address2: Not shown in title block; Address3: Not shown in title block; Address4: Not shown in title block; DocumentNumber: 4; Revision: Use project parameter SCH_Rev; SheetNumber: 4; SheetTotal: 7; PageSetup: Record=PageOptions¦CenterHorizontal=True¦CenterVertical=True¦PrintScale=1.00¦XCorrection=1.00¦YCorrection=1.00¦PrintKind=0¦BorderSize=5000000¦LeftOffset=0¦BottomOffset=0¦Orientation=2¦PaperLength=1000¦PaperWidth=1000¦Scale=100¦PaperSource=15¦PrintQuality=600¦MediaType=1¦DitherType=10¦PaperKind=Letter¦PrintScaleMode=1
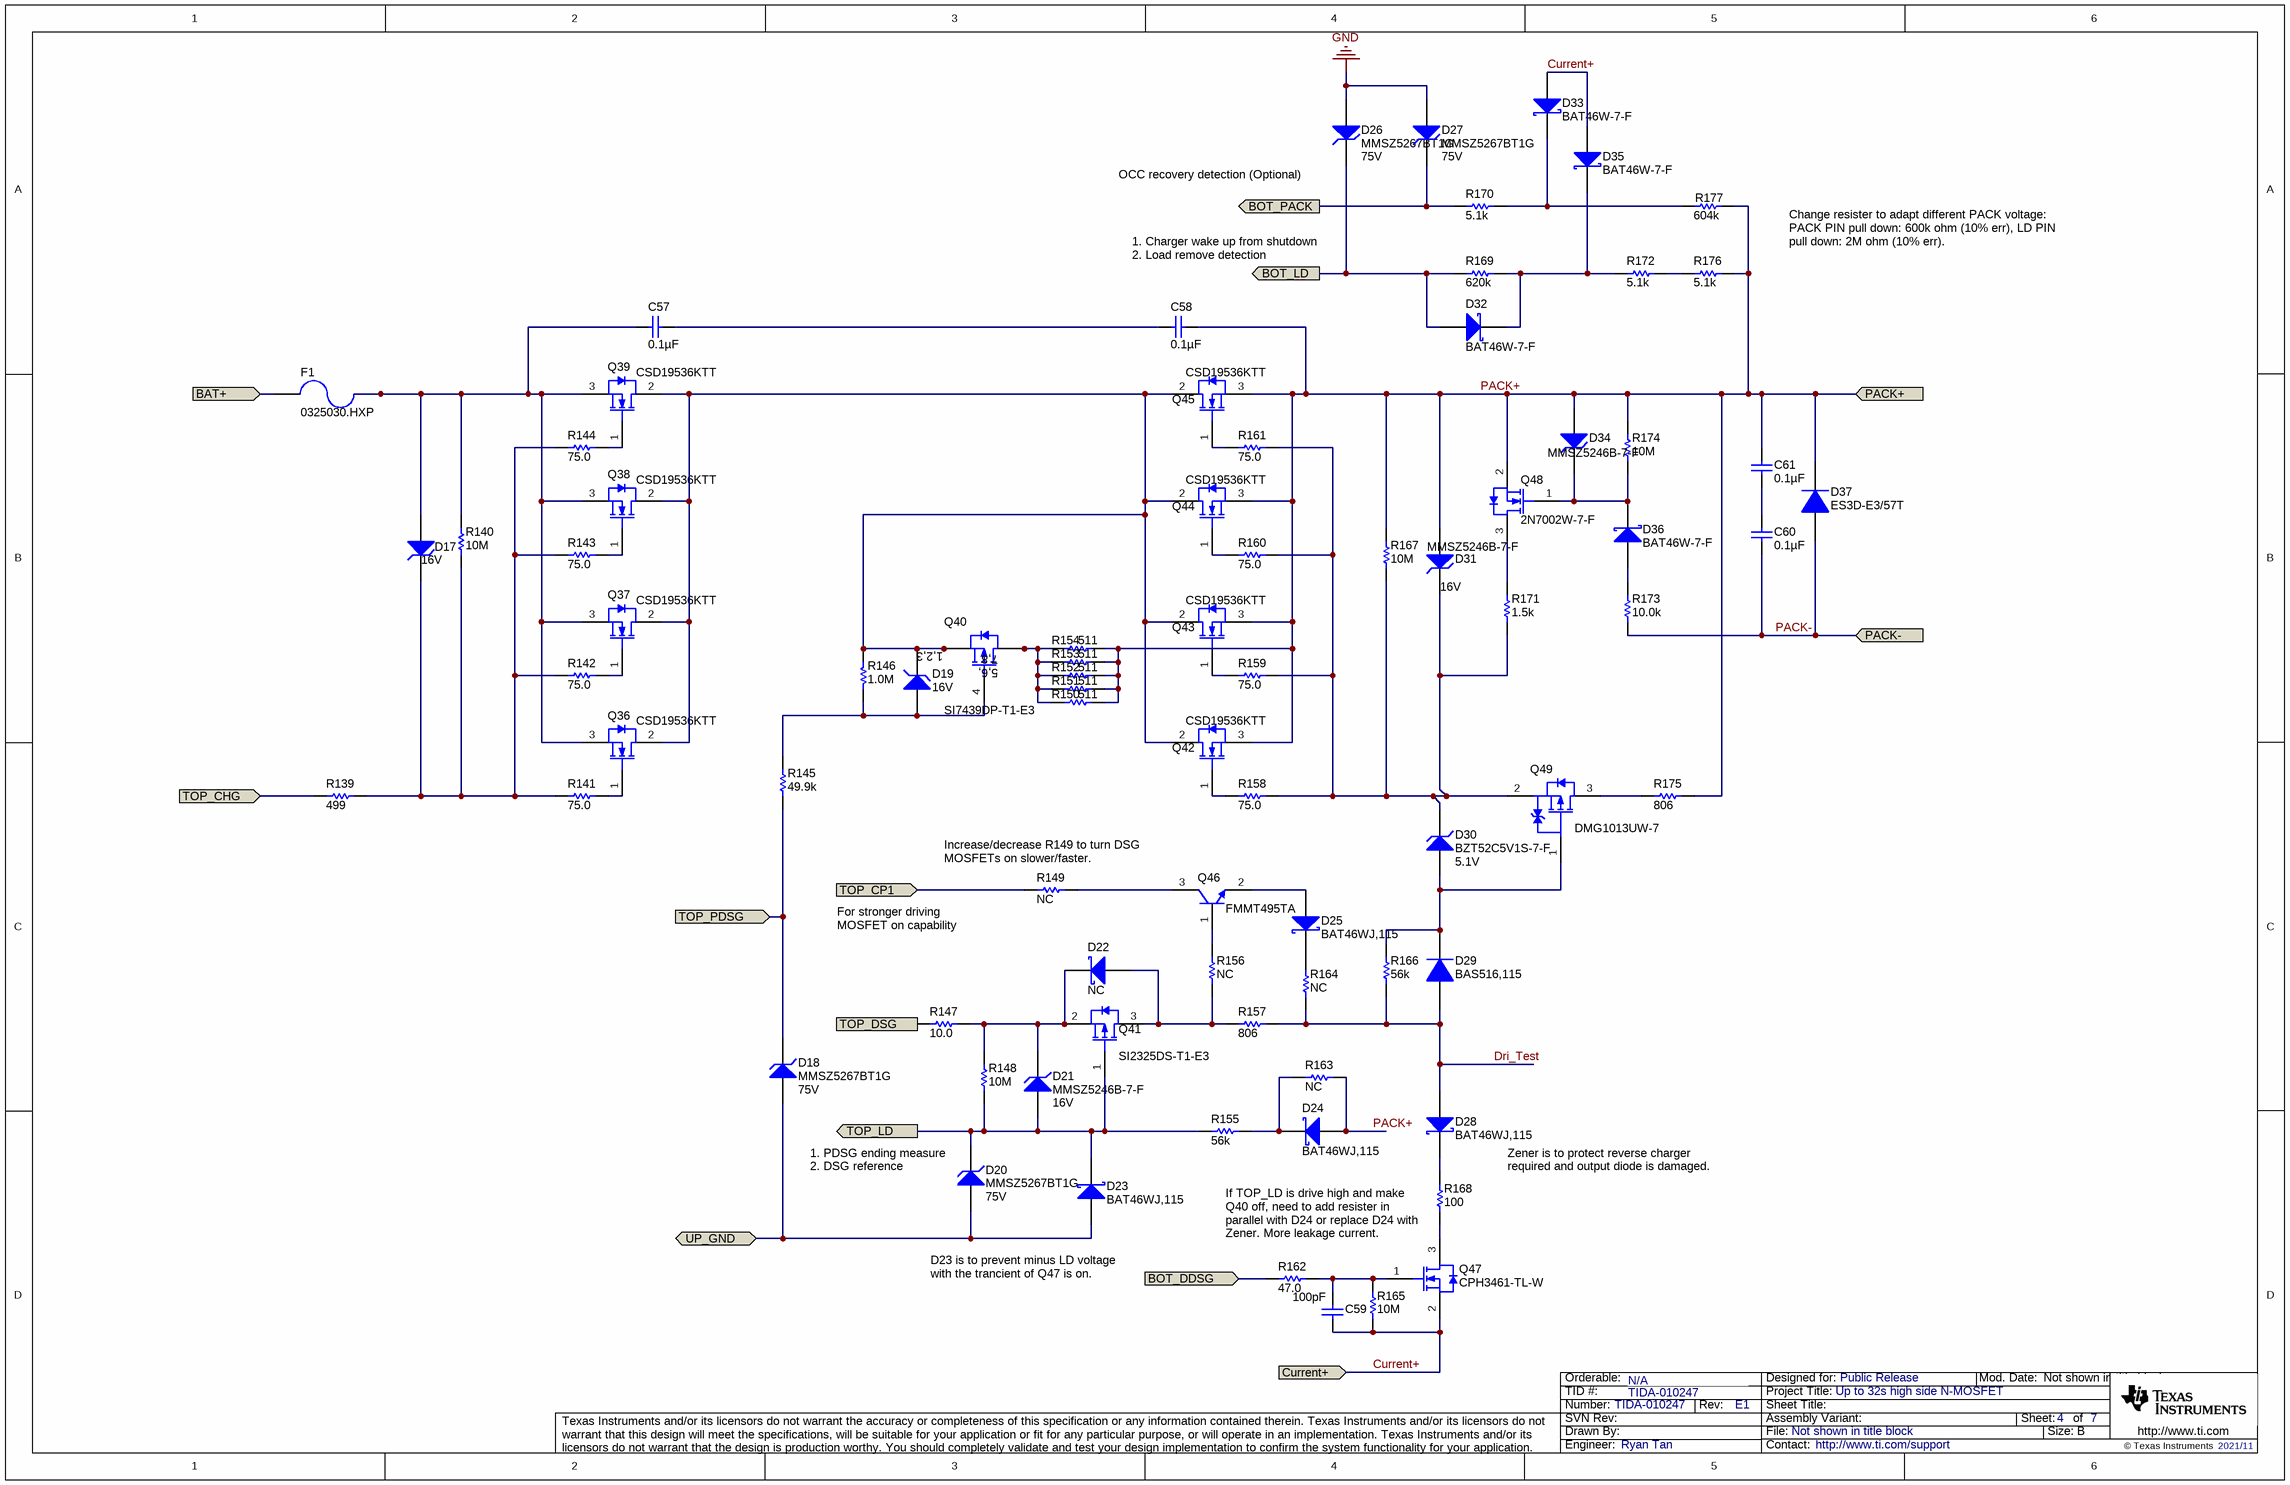
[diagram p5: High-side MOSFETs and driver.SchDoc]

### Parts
C57  ValueDisplayed: 0.1µF  [0603]  (hidden comment: GRM188R72A104KA35D)
C58  ValueDisplayed: 0.1µF  [0603]  (hidden comment: GRM188R72A104KA35D)
C59  ValueDisplayed: 100pF  [0603]  (hidden comment: GRM1885C2A101JA01D)
C60  ValueDisplayed: 0.1µF  [0603]  (hidden comment: GRM188R72A104KA35D)
C61  ValueDisplayed: 0.1µF  [0603]  (hidden comment: GRM188R72A104KA35D)
D17  value 16V  [SOD-123]  (hidden comment: MMSZ5246B-7-F)
D18  MMSZ5267BT1G  value 75V  [SOD-123]
D19  value 16V  [SOD-123]  (hidden comment: MMSZ5246B-7-F)
D20  MMSZ5267BT1G  value 75V  [SOD-123]
D21  MMSZ5246B-7-F  value 16V  [SOD-123]
D22  NC  [SOD-323F]
D23  BAT46WJ,115  [SOD-323F]
D24  BAT46WJ,115  [SOD-323F]
D25  BAT46WJ,115  [SOD-323F]
D26  MMSZ5267BT1G  value 75V  [SOD-123]
D27  MMSZ5267BT1G  value 75V  [SOD-123]
D28  BAT46WJ,115  [SOD-323F]
D29  BAS516,115  [SOD-523]
D30  BZT52C5V1S-7-F  value 5.1V  [SOD-323]
D31  MMSZ5246B-7-F  value 16V  [SOD-123]
D32  BAT46W-7-F  [SOD-123]
D33  BAT46W-7-F  [SOD-123]
D34  MMSZ5246B-7-F  [SOD-123]
D35  BAT46W-7-F  [SOD-123]
D36  BAT46W-7-F  [SOD-123]
D37  ES3D-E3/57T  [SMC]
F1  0325030.HXP  [0325030]
Q36  CSD19536KTT  [KTT0002A_N]
Q37  CSD19536KTT  [KTT0002A_N]
Q38  CSD19536KTT  [KTT0002A_N]
Q39  CSD19536KTT  [KTT0002A_N]
Q40  SI7439DP-T1-E3  [PowerPAK_SO-8]
Q41  SI2325DS-T1-E3  [SOT-23]
Q42  CSD19536KTT  [KTT0002A_N]
Q43  CSD19536KTT  [KTT0002A_N]
Q44  CSD19536KTT  [KTT0002A_N]
Q45  CSD19536KTT  [KTT0002A_N]
Q46  FMMT495TA  [SOT-23]
Q47  CPH3461-TL-W  [SOT-23]
Q48  2N7002W-7-F  [SOT-323]
Q49  DMG1013UW-7  [SOT-323]
R139  ValueDisplayed: 499  [0603]  (hidden comment: RC0603FR-07499RL)
R140  ValueDisplayed: 10M  [0603]  (hidden comment: CRCW060310M0JNEA)
R141  ValueDisplayed: 75.0  [0603]  (hidden comment: CRCW060375R0FKEA)
R142  ValueDisplayed: 75.0  [0603]  (hidden comment: CRCW060375R0FKEA)
R143  ValueDisplayed: 75.0  [0603]  (hidden comment: CRCW060375R0FKEA)
R144  ValueDisplayed: 75.0  [0603]  (hidden comment: CRCW060375R0FKEA)
R145  ValueDisplayed: 49.9k  [0603]  (hidden comment: RT0603BRD0749K9L)
R146  ValueDisplayed: 1.0M  [0603]  (hidden comment: CRCW06031M00JNEA)
R147  ValueDisplayed: 10.0  [0805_HV]  (hidden comment: CRCW080510R0FKEA)
R148  ValueDisplayed: 10M  [0603]  (hidden comment: CRCW060310M0JNEA)
R149  NC  [0603]
R150  ValueDisplayed: 511  [1206]  (hidden comment: RC1206FR-07511RL)
R151  ValueDisplayed: 511  [1206]  (hidden comment: RC1206FR-07511RL)
R152  ValueDisplayed: 511  [1206]  (hidden comment: RC1206FR-07511RL)
R153  ValueDisplayed: 511  [1206]  (hidden comment: RC1206FR-07511RL)
R154  ValueDisplayed: 511  [1206]  (hidden comment: RC1206FR-07511RL)
R155  ValueDisplayed: 56k  [0805_HV]  (hidden comment: RC0805JR-0756KL)
R156  NC  [0603]
R157  ValueDisplayed: 806  [0805_HV]  (hidden comment: AC0805FR-07806RL)
R158  ValueDisplayed: 75.0  [0603]  (hidden comment: CRCW060375R0FKEA)
R159  ValueDisplayed: 75.0  [0603]  (hidden comment: CRCW060375R0FKEA)
R160  ValueDisplayed: 75.0  [0603]  (hidden comment: CRCW060375R0FKEA)
R161  ValueDisplayed: 75.0  [0603]  (hidden comment: CRCW060375R0FKEA)
R162  ValueDisplayed: 47.0  [0603]  (hidden comment: RC0603FR-0747RL)
R163  NC  [0603]
R164  ValueDisplayed: NC  [0603]  (hidden comment: CRCW06030000Z0EA)
R165  ValueDisplayed: 10M  [0603]  (hidden comment: CRCW060310M0JNEA)
R166  ValueDisplayed: 56k  [0805_HV]  (hidden comment: RC0805JR-0756KL)
R167  ValueDisplayed: 10M  [0603]  (hidden comment: CRCW060310M0JNEA)
R168  ValueDisplayed: 100  [0805_HV]  (hidden comment: CRCW0805100RFKEA)
R169  ValueDisplayed: 620k  [0603]  (hidden comment: RC0603FR-07620KL)
R170  ValueDisplayed: 5.1k  [0603]  (hidden comment: CRCW06035K10JNEA)
R171  ValueDisplayed: 1.5k  [0805_HV]  (hidden comment: AC0805JR-071K5L)
R172  ValueDisplayed: 5.1k  [0603]  (hidden comment: CRCW06035K10JNEA)
R173  ValueDisplayed: 10.0k  [0603]  (hidden comment: CRCW060310K0FKEA)
R174  ValueDisplayed: 10M  [0603]  (hidden comment: CRCW060310M0JNEA)
R175  ValueDisplayed: 806  [0603]  (hidden comment: CRCW0603806RFKEA)
R176  ValueDisplayed: 5.1k  [0603]  (hidden comment: CRCW06035K10JNEA)
R177  ValueDisplayed: 604k  [0603]  (hidden comment: RC0603FR-07604KL)

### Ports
BAT+ (in), BOT_DDSG (in), BOT_LD (out), BOT_PACK (out), Current+ (in), PACK+ (in), PACK- (in), TOP_CHG (in), TOP_CP1 (in), TOP_DSG (in), TOP_LD (out), TOP_PDSG (in), UP_GND (bidir)

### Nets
GND: D26.2(A) D27.2(A)
UP_GND: D18.2(A) D20.2(A) D23.2(A) ; port UP_GND
BAT+: F1.2 ; port BAT+
BOT_DDSG: R162.1 ; port BOT_DDSG
BOT_LD: D26.1(K) D32.2(A) R169.1 ; port BOT_LD
BOT_PACK: D27.1(K) R170.1 ; port BOT_PACK
Current+: C59.2 D33.2(A) D35.2(A) Q47.2(S) R165.1 ; port Current+
Dri_Test: D28.2(A) D29.2(A) R157.1 R164.1 R166.1
PACK+: C58.1 C61.1 D24.2(A) D31.2(A) D34.2(A) D37.1(K) Q42.3(S) Q43.3(S) Q44.3(S) Q45.3(S) Q48.2(S) R150.2 R151.2 R152.2 R153.2 R154.2 R163.1 R167.2 R174.1 R175.2 R176.2 R177.2 ; port PACK+
PACK-: C60.2 D37.2(A) R173.1 ; port PACK-
TOP_CHG: R139.1 ; port TOP_CHG
TOP_CP1: R149.1 ; port TOP_CP1
TOP_DSG: R147.2 ; port TOP_DSG
TOP_LD: D20.1(K) D21.2(A) D23.1(K) Q41.1(G) R148.1 R155.2 ; port TOP_LD
TOP_PDSG: D18.1(K) R145.1 ; port TOP_PDSG
NetC57_1: C57.1 C58.2
NetC57_2: C57.2 D17.2(A) F1.1 Q36.3(S) Q37.3(S) Q38.3(S) Q39.3(S) R140.2
NetC59_1: C59.1 Q47.1(G) R162.2 R165.2
NetC60_1: C60.1 C61.2
NetD17_1: D17.1(K) R139.2 R140.1 R141.1 R142.1 R143.1 R144.1
NetD19_1: D19.1(K) Q36.2(D) Q37.2(D) Q38.2(D) Q39.2(D) Q40.1(S) Q40.2(S) Q40.3(S) Q42.2(D) Q43.2(D) Q44.2(D) Q45.2(D) R146.1
NetD19_2: D19.2(A) Q40.4(G) R145.2 R146.2
NetD21_1: D21.1(K) D22.1(K) Q41.2(S) R147.1 R148.2
NetD22_2: D22.2(A) Q41.3(D) R156.1 R157.2
NetD24_1: D24.1(K) R155.1 R163.2
NetD25_1: D25.1(K) R164.2
NetD25_2: D25.2(A) Q46.2(E)
NetD28_1: D28.1(K) R168.2
NetD29_1: D29.1(K) D30.2(A) Q49.1(G) R166.2
NetD30_1: D30.1(K) D31.1(K) Q49.2(S) R158.2 R159.2 R160.2 R161.2 R167.1 R171.1
NetD32_1: D32.1(K) D35.1(K) R169.2 R172.1
NetD33_1: D33.1(K) R170.2 R177.1
NetD34_1: D34.1(K) D36.1(K) Q48.1(G) R174.2
NetD36_2: D36.2(A) R173.2
NetQ36_1: Q36.1(G) R141.2
NetQ37_1: Q37.1(G) R142.2
NetQ38_1: Q38.1(G) R143.2
NetQ39_1: Q39.1(G) R144.2
NetQ40_5: Q40.5(D) Q40.6(D) Q40.7(D) Q40.8(D) Q40.9(D) R150.1 R151.1 R152.1 R153.1 R154.1
NetQ42_1: Q42.1(G) R158.1
NetQ43_1: Q43.1(G) R159.1
NetQ44_1: Q44.1(G) R160.1
NetQ45_1: Q45.1(G) R161.1
NetQ46_1: Q46.1(B) R156.2
NetQ46_3: Q46.3(C) R149.2
NetQ47_3: Q47.3(D) R168.1
NetQ48_3: Q48.3(D) R171.2
NetQ49_3: Q49.3(D) R175.1
NetR172_2: R172.2 R176.1

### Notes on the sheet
- (near D26) OCC recovery detection (Optional)
- 1. Charger wake up from shutdown
  2. Load remove detection
- Change resister to adapt different PACK voltage: PACK PIN pull down: 600k ohm (10% err), LD PIN pull down: 2M ohm (10% err).
- Increase/decrease R149 to turn DSG MOSFETs on slower/faster.
- For stronger driving MOSFET on capability
- (near D20) 1. PDSG ending measure
  2. DSG reference
- (near R168) If TOP_LD is drive high and make Q40 off, need to add resister in parallel with D24 or replace D24 with Zener. More leakage current.
- Zener is to protect reverse charger required and output diode is damaged.
- D23 is to prevent minus LD voltage with the trancient of Q47 is on.
- N/A

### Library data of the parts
C57 C58 C60 C61 = GRM188R72A104KA35D: as C73 on sheet Aux power
C59 = GRM1885C2A101JA01D: as C77 on sheet Aux power
D17 D19 D21 D31 = MMSZ5246B-7-F: Diode, Zener, 16 V, 500 mW, SOD-123; Manufacturer: Diodes Inc.; SymbolCreator: a0412235; U/M: EA; Power_W: 0.5; Vz_V: 16; Value1: 0.5W; RJA_CperW: 350; SizeAreaWB_mm2: 13.095; SizeArea_mm2: 6.545; SizeX_mm: 3.85; SizeY_mm: 1.7; SizeZ_mm: 1.35; AEC Category: Q101; Green_Lifecycle: Active; Green_REACh: Passed
D18 D20 D26 D27 = MMSZ5263BT1G: Diode, Zener, 75V, 500 mW, AEC-Q101, SOD-123; Manufacturer: ON Semiconductor; SymbolCreator: a0412235; U/M: EA; Power_W: 0.5; Vz_V: 56; Value1: 0.5W; RJA_CperW: 340; SizeAreaWB_mm2: 13.095; SizeArea_mm2: 6.545; SizeX_mm: 3.85; SizeY_mm: 1.7; SizeZ_mm: 1.35; AEC Category: Q101; AEC Qualified: Y
D22-D25 D28 = BAT46WJ,115: as D38 on sheet MCU and Communication
D29 = BAS516,115: as D48 on sheet Aux power
D30 = BZT52C5V1S-7-F: Diode, Zener, 5.1 V, 200 mW, SOD-323; Manufacturer: Diodes Inc.; SymbolCreator: a0412235; U/M: EA; Power_W: 0.2; Vz_V: 5.1; Value1: 0.2W; RJA_CperW: 625; SizeAreaWB_mm2: 8.695; SizeArea_mm2: 3.645; SizeX_mm: 2.7; SizeY_mm: 1.35; SizeZ_mm: 1; AEC Category: Q101; Green_Lifecycle: Active; Green_REACh: Passed
D32 D33 D35 D36 = BAT46W-7-F: Diode, Schottky, 100 V, 0.15 A, SOD-123; Manufacturer: Diodes Inc.; U/M: EA; Vf_V: 0.6; Value: 100V; Value1: 0.15A; Value2: 0.6V; Io_A: 0.15; Vr_V: 100; SizeAreaWB_mm2: 13.095; SizeArea_mm2: 6.545; SizeX_mm: 3.85; SizeY_mm: 1.7; SizeZ_mm: 1.35; AEC Category: Q101; Green_Lifecycle: Active; Green_REACh: Passed
D34 = MMSZ5246B-7-F: Diode, Zener, 16 V, 500 mW, SOD-123; Manufacturer: Diodes Inc.; SymbolCreator: a0412235; Value: 16V; U/M: EA; Power_W: 0.5; Vz_V: 16; Value1: 0.5W; RJA_CperW: 350; SizeAreaWB_mm2: 13.095; SizeArea_mm2: 6.545; SizeX_mm: 3.85; SizeY_mm: 1.7; SizeZ_mm: 1.35; AEC Category: Q101; Green_Lifecycle: Active; Green_REACh: Passed
D37 = ES3D-E3/57T: Diode, Ultrafast, 200 V, 3 A, SMC; Manufacturer: Vishay-Semiconductor; U/M: EA; Vf_V: 0.9; Value: 200V; Value1: 3A; Value2: 0.9V; Io_A: 3; Vr_V: 200; TJmax_C: 150; SizeAreaWB_mm2: 83.2686; SizeArea_mm2: 50.5686; SizeX_mm: 8.13; SizeY_mm: 6.22; SizeZ_mm: 2.6; AEC Category: Q101; Green_Lifecycle: Not Set; Green_REACh: Incomplete
F1 = 0325030: Fuse, 30 A, 250 VAC, 125 VDC, TH; Manufacturer: LittleFuse
Q36-Q39 Q42-Q45 = CSD19536KTT: MOSFET, N-CH, 100 V, 200 A, KTT0002A (TO-263-2); Manufacturer: Texas Instruments; Alternate Manufacturer: None; U/M: EA; ChType: N; Value: 100V; VdsMax_V: 100; Value1: ? ohm; Value2: 118 nC; QgTyp_nC: 118; Vgs_V: 20; IdsMax_A: 200; SizeAreaWB_mm2: 198.208; SizeArea_mm2: 145.288; SizeX_mm: 14.3; SizeY_mm: 10.16; SizeZ_mm: 4.7; AEC Category: Q101
Q40 = SI7439DP-T1-E3: MOSFET, P-CH, -150 V, -3 A, PowerPAK SO-8; Manufacturer: Vishay-Siliconix; Alternate Manufacturer: None; U/M: EA; ChType: P; Value: -150V; Value1: ? ohm; Value2: 88 nC; QgTyp_nC: 88; Vgs_V: -20; SizeAreaWB_mm2: 55.131; SizeArea_mm2: 29.351; SizeX_mm: 5.99; SizeY_mm: 4.9; SizeZ_mm: 1.12; AEC Category: Q101; Green_Lifecycle: Active; Green_REACh: Passed
Q41 = SI2325DS-T1-E3: MOSFET, P-CH, -150 V, -0.53 A, SOT-23; Manufacturer: Vishay-Siliconix; Alternate Manufacturer: None; U/M: EA; ChType: P; Value: -150V; Value1: ? ohm; Value2: 7.7 nC; QgTyp_nC: 7.7; Vgs_V: -20; SizeAreaWB_mm2: 14; SizeArea_mm2: 7.5; SizeX_mm: 2.5; SizeY_mm: 3; SizeZ_mm: 1.1; AEC Category: Q101; AEC Qualified: N; Green_Lifecycle: Active; Green_REACh: Passed
Q46 = FMMT495TA, Diodes Inc.: Transistor, NPN, 150 V, 1 A, AEC-Q101, SOT-23; CompType: BJT; PNP: 0; NPN: 1; Vceo_V: 150; Vcesat1_V: 0.3; Value: 150 V; Value1: 1 A; HfeMax: 300; TaMin_C: -55; SizeAreaWB_mm2: 14; SizeArea_mm2: 7.5; SizeX_mm: 2.5; SizeY_mm: 3; SizeZ_mm: 1.1; U/M: EA; AEC Category: Q101; AEC Qualified: Y
Q47 = BSS123: MOSFET, N-CH, 250V, 0.35 A, SOT-23; Manufacturer: Fairchild Semiconductor; Alternate Manufacturer: None; U/M: EA; ChType: N; VdsMax_V: 100; Value1: 10 ohm; Rdson45_ohm: 10; Value2: 1.8 nC; QgTyp_nC: 1.8; Vgs_V: 20; IdsMax_A: 0.17; SizeAreaWB_mm2: 14; SizeArea_mm2: 7.5; SizeX_mm: 2.5; SizeY_mm: 3; SizeZ_mm: 1.1; AEC Category: Q101; Green_Lifecycle: Active; Green_REACh: Passed
Q48 = 2N7002W-7-F: MOSFET, N-CH, 60 V, 0.115 A, SOT-323; Manufacturer: Diodes Inc.; Alternate Manufacturer: None; U/M: EA; ChType: N; Value: 60V; VdsMax_V: 60; Value1: 7.5 ohm; Rdson45_ohm: 7.5; Value2: ? nC; Vgs_V: 20; IdsMax_A: 0.115; SizeAreaWB_mm2: 10.24; SizeArea_mm2: 4.84; SizeX_mm: 2.2; SizeZ_mm: 1.1; AEC Category: Q101; Green_Lifecycle: Active; Green_REACh: Passed
Q49 = DMG1013UW-7: MOSFET, P-CH, -20 V, -0.82 A, SOT-323; Manufacturer: Diodes Inc.; Alternate Manufacturer: None; SymbolCreator: a0411947; U/M: EA; ChType: P; Value: -20V; Value1: 0.75 ohm; Rdson45_ohm: 0.75; Value2: 0.622 nC; QgTyp_nC: 0.622; Vgs_V: -6; SizeAreaWB_mm2: 10.24; SizeArea_mm2: 4.84; SizeX_mm: 2.2; SizeZ_mm: 1.1; AEC Category: Q101; Green_Lifecycle: Active; Green_REACh: Passed
R139 = RC0603FR-07499RL: as R189 on sheet MCU and Communication
R140 R148 R165 R167 R174 = CRCW060310M0JNEA: RES, 10 M, 5%, 0.1 W, 0603; Manufacturer: Vishay-Dale; CompType: Resistor; Value: 10Meg; Res_ohm: 10000000; Value_Code: 10M0; Tolerance_%: 5; Power_W: 0.1; Value2: 0.1W; VDC_V: 75; TempCo: 200 ppm/C; SizeArea_mm2: 1.28; SizeX_mm: 1.6; SizeY_mm: 0.8; SizeZ_mm: 1; EIA_Code: E24; U/M: EA; AEC Category: Q200; Green_Lifecycle: Active; Green_REACh: Passed
R141-R144 R158-R161 = CRCW060375R0FKEA: RES, 75.0, 1%, 0.1 W, 0603; Manufacturer: Vishay-Dale; CompType: Resistor; Value: 75.0; Res_ohm: 75; Value_Code: 75R0; Tolerance_%: 1; Power_W: 0.1; Value2: 0.1W; TempCo: 100 ppm/C; SizeArea_mm2: 1.28; SizeX_mm: 1.6; SizeY_mm: 0.8; EIA_Code: E96; U/M: EA; AEC Category: Q200; Green_Lifecycle: Active; Green_REACh: Passed
R145 = RT0603BRD0749K9L: RES, 49.9 k, 0.1%, 0.1 W, 0603; Manufacturer: Yageo America; CompType: Resistor; Value: 49.9k; Res_ohm: 49900; Value_Code: 49k9; Tolerance_%: 0.1; Value2: 0.1W; VDC_V: 75; TempCo: 25 ppm/C; SizeArea_mm2: 1.28; SizeX_mm: 1.6; SizeY_mm: 0.8; SizeZ_mm: 1; EIA_Code: E192; U/M: EA; AEC Category: Q200
R146 = CRCW06031M00JNEA: RES, 1.0 M, 5%, 0.1 W, 0603; Manufacturer: Vishay-Dale; CompType: Resistor; Value: 1.0Meg; Res_ohm: 1000000; Value_Code: 1M00; Tolerance_%: 5; Power_W: 0.1; Value2: 0.1W; VDC_V: 75; TempCo: 200 ppm/C; SizeArea_mm2: 1.28; SizeX_mm: 1.6; SizeY_mm: 0.8; SizeZ_mm: 1; EIA_Code: E24; U/M: EA; AEC Category: Q200; Green_Lifecycle: Active; Green_REACh: Passed
R147 = CRCW080510R0FKEA: RES, 10.0, 1%, 0.125 W, 0805; Manufacturer: Vishay-Dale; CompType: Resistor; Value: 10.0; Res_ohm: 10; Value_Code: 10R0; Tolerance_%: 1; Power_W: 0.125; Value2: 0.125W; VDC_V: 150; TempCo: 100 ppm/C; SizeArea_mm2: 2.5; SizeX_mm: 2; SizeY_mm: 1.25; SizeZ_mm: 1.45; EIA_Code: E96; U/M: EA; AEC Category: Q200; Green_Lifecycle: Active; Green_REACh: Passed
R149 = CRCW0603390RFKEA: RES, 390, 1%, 0.1 W, 0603; Manufacturer: Vishay-Dale; CompType: Resistor; Value: 390; Value_Code: 390R; Tolerance_%: 1; Power_W: 0.1; Value2: 0.1W; VDC_V: 75; TempCo: 100 ppm/C; SizeArea_mm2: 1.28; SizeX_mm: 1.6; SizeY_mm: 0.8; U/M: EA; AEC Category: Q200
R150-R154 = CRCW1206511RFKEA: RES, 511, 1%, 0.25 W, 1206; Manufacturer: Yageo; CompType: Resistor; Value: 511; Value_Code: 511R; Tolerance_%: 1; Power_W: 0.25; Value2: 0.25W; VDC_V: 200; TempCo: 100 ppm/C; SizeArea_mm2: 5.12; SizeX_mm: 3.2; SizeY_mm: 1.6; SizeZ_mm: 1.35; EIA_Code: E96; U/M: EA; AEC Category: Q200
R155 R166 = CRCW080556K0JNEA: RES, 56 k, 5%, 0.125 W, 0805; Manufacturer: Yageo; CompType: Resistor; Value: 56k; Res_ohm: 56000; Value_Code: 56k0; Tolerance_%: 5; Power_W: 0.125; Value2: 0.125W; VDC_V: 150; TempCo: 200 ppm/C; SizeArea_mm2: 2.5; SizeX_mm: 2; SizeY_mm: 1.25; SizeZ_mm: 1.45; EIA_Code: E24; U/M: EA; AEC Category: Q200
R156 R175 = CRCW0603806RFKEA: RES, 806, 1%, 0.1 W, 0603; Manufacturer: Vishay-Dale; CompType: Resistor; Value: 806; Value_Code: 806R; Tolerance_%: 1; Power_W: 0.1; Value2: 0.1W; VDC_V: 75; TempCo: 100 ppm/C; SizeArea_mm2: 1.28; SizeX_mm: 1.6; SizeY_mm: 0.8; EIA_Code: E96; U/M: EA; AEC Category: Q200; Green_Lifecycle: Active; Green_REACh: Passed
R157 = CRCW0805806RFKEA: RES, 806, 1%, 0.125 W, 0805; Manufacturer: Yageo; CompType: Resistor; Value: 806; Value_Code: 806R; Tolerance_%: 1; Power_W: 0.125; Value2: 0.125W; VDC_V: 150; TempCo: 100 ppm/C; SizeArea_mm2: 2.5; SizeX_mm: 2; SizeY_mm: 1.25; SizeZ_mm: 1.45; EIA_Code: E96; U/M: EA; AEC Category: Q200
R162 = RC0603FR-0747RL: RES, 47.0, 1%, 0.1 W, 0603; Manufacturer: Yageo America; CompType: Resistor; Value: 47.0; Res_ohm: 47; Value_Code: 47R0; Tolerance_%: 1; Power_W: 0.1; Value2: 0.1W; VDC_V: 150; TempCo: 200 ppm/C; SizeArea_mm2: 1.28; SizeX_mm: 1.6; SizeY_mm: 0.8; U/M: EA; AEC Category: Q200; Green_Lifecycle: Active; Green_REACh: Passed
R163 = CRCW060310M0JNEA: RES, 10 M, 5%, 0.1 W, 0603; Manufacturer: Vishay-Dale; CompType: Resistor; Value: 10M; Res_ohm: 10000000; Value_Code: 10M0; Tolerance_%: 5; Power_W: 0.1; Value2: 0.1W; VDC_V: 75; TempCo: 200 ppm/C; SizeArea_mm2: 1.28; SizeX_mm: 1.6; SizeY_mm: 0.8; SizeZ_mm: 1; EIA_Code: E24; U/M: EA; AEC Category: Q200; Green_Lifecycle: Active; Green_REACh: Passed
R164 = CRCW06030000Z0EA: RES, 0, 5%, 0.1 W, 0603; Manufacturer: Vishay-Dale; CompType: Resistor; Value: NC; Res_ohm: 0; Value_Code: 0000; Tolerance_%: 5; Power_W: 0.1; Value2: 0.1W; VDC_V: 75; TempCo: 200 ppm/C; SizeArea_mm2: 1.28; SizeX_mm: 1.6; SizeY_mm: 0.8; SizeZ_mm: 1; EIA_Code: E24; U/M: EA; AEC Category: Q200; Green_Lifecycle: Active; Green_REACh: Passed
R168 = CRCW0805100RFKEA: RES, 100, 1%, 0.125 W, 0805; Manufacturer: Vishay-Dale; CompType: Resistor; Value: 100; Value_Code: 100R; Tolerance_%: 1; Power_W: 0.125; Value2: 0.125W; VDC_V: 150; TempCo: 100 ppm/C; SizeArea_mm2: 2.5; SizeX_mm: 2; SizeY_mm: 1.25; SizeZ_mm: 1.45; EIA_Code: E96; U/M: EA; AEC Category: Q200; Green_Lifecycle: Active; Green_REACh: Passed
R169 = RC0603FR-07620KL: RES, 620 k, 1%, 0.1 W, 0603; Manufacturer: Yageo America; CompType: Resistor; Value: 620k; Res_ohm: 620000; Tolerance_%: 1; Power_W: 0.1; Value2: 0.1W; VDC_V: 150; TempCo: 200 ppm/C; SizeArea_mm2: 1.28; SizeX_mm: 1.6; SizeY_mm: 0.8; U/M: EA; AEC Category: Q200; Green_Lifecycle: Active; Green_REACh: Passed
R170 R172 R176 = CRCW06035K10JNEA: RES, 5.1 k, 5%, 0.1 W, 0603; Manufacturer: Vishay-Dale; CompType: Resistor; Value: 5.1k; Res_ohm: 5100; Value_Code: 5k10; Tolerance_%: 5; Power_W: 0.1; Value2: 0.1W; VDC_V: 75; TempCo: 200 ppm/C; SizeArea_mm2: 1.28; SizeX_mm: 1.6; SizeY_mm: 0.8; SizeZ_mm: 1; EIA_Code: E24; U/M: EA; AEC Category: Q200; Green_Lifecycle: Active; Green_REACh: Passed
R171 = CRCW08051K50JNEA: RES, 1.5 k, 5%, 0.125 W, 0805; Manufacturer: Yageo; CompType: Resistor; Value: 1.5k; Res_ohm: 1500; Value_Code: 1k50; Tolerance_%: 5; Power_W: 0.125; Value2: 0.125W; VDC_V: 150; TempCo: 200 ppm/C; SizeArea_mm2: 2.5; SizeX_mm: 2; SizeY_mm: 1.25; SizeZ_mm: 1.45; EIA_Code: E24; U/M: EA; AEC Category: Q200
R173 = CRCW060310K0FKEA: as R179 on sheet MCU and Communication
R177 = RC0603FR-07604KL: RES, 604 k, 1%, 0.1 W, 0603; Manufacturer: Yageo America; CompType: Resistor; Value: 604k; Res_ohm: 604000; Tolerance_%: 1; Power_W: 0.1; Value2: 0.1W; VDC_V: 150; TempCo: 200 ppm/C; SizeArea_mm2: 1.28; SizeX_mm: 1.6; SizeY_mm: 0.8; EIA_Code: E96; U/M: EA; AEC Category: Q200; Green_Lifecycle: Active; Green_REACh: Passed

## Sheet EVM_Hardware.SchDoc
size 431 x 279 mm; Date: Not shown in title block; ApprovedBy: Not shown in title block; CheckedBy: Not shown in title block; Author: Not shown in title block; CompanyName: Not shown in title block; Engineer: Not shown in title block; Organization: Not shown in title block; Address1: Not shown in title block; Address2: Not shown in title block; Address3: Not shown in title block; Address4: Not shown in title block; DocumentNumber: 7; Revision: Use project parameter SCH_Rev; SheetNumber: 7; SheetTotal: 7; PageSetup: Record=PageOptions¦CenterHorizontal=True¦CenterVertical=True¦PrintScale=1.00¦XCorrection=1.00¦YCorrection=1.00¦PrintKind=0¦BorderSize=5000000¦LeftOffset=0¦BottomOffset=0¦Orientation=2¦PaperLength=1000¦PaperWidth=1000¦Scale=100¦PaperSource=15¦PrintQuality=600¦MediaType=1¦DitherType=10¦PaperKind=Letter¦PrintScaleMode=1
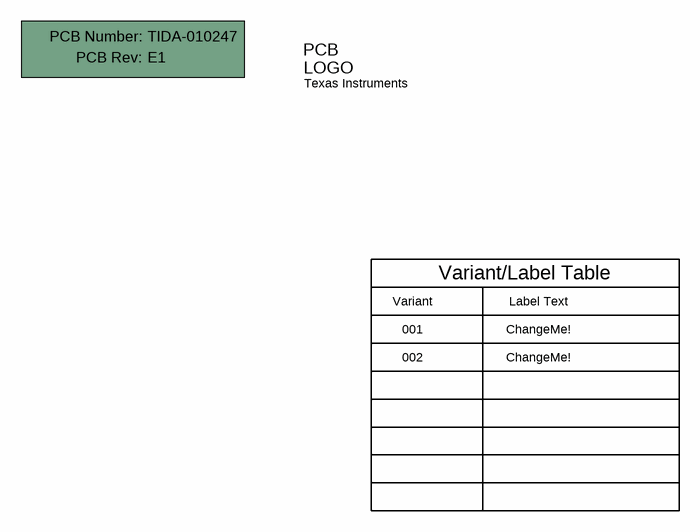
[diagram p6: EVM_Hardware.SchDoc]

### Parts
!PCB1  Printed Circuit Board  (value not drawn)  (mechanical)
Logo1  Texas Instruments  [TI_Stacked_Overlay_Small]  (no BOM)

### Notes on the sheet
- Variant
- Variant/Label Table
- Label Text
- 001
- 002
- ChangeMe!

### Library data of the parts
!PCB1 = CMP-0003618-2: Manufacturer: Any; PartNumber: TIDA-010247
Logo1 = CMP-0074838-1: Texas Instrument Corporate Signature; SymbolCreator: a0412235; Lib Reference: TI_Logo; Library Reference: Logo

## Sheet CoverSheet.SchDoc
size 431 x 279 mm; Date: Not shown in title block; ApprovedBy: Not shown in title block; CheckedBy: Not shown in title block; Author: Not shown in title block; CompanyName: Not shown in title block; Engineer: Not shown in title block; Organization: Not shown in title block; Address1: Not shown in title block; Address2: Not shown in title block; Address3: Not shown in title block; Address4: Not shown in title block; DocumentNumber: 1; Revision: Use project parameter SCH_Rev; SheetNumber: 1; SheetTotal: 7; PageSetup: Record=PageOptions¦CenterHorizontal=True¦CenterVertical=True¦PrintScale=1.00¦XCorrection=1.00¦YCorrection=1.00¦PrintKind=0¦BorderSize=5000000¦LeftOffset=0¦BottomOffset=0¦Orientation=2¦PaperLength=1000¦PaperWidth=1000¦Scale=100¦PaperSource=15¦PrintQuality=600¦MediaType=1¦DitherType=10¦PaperKind=Letter¦PrintScaleMode=1
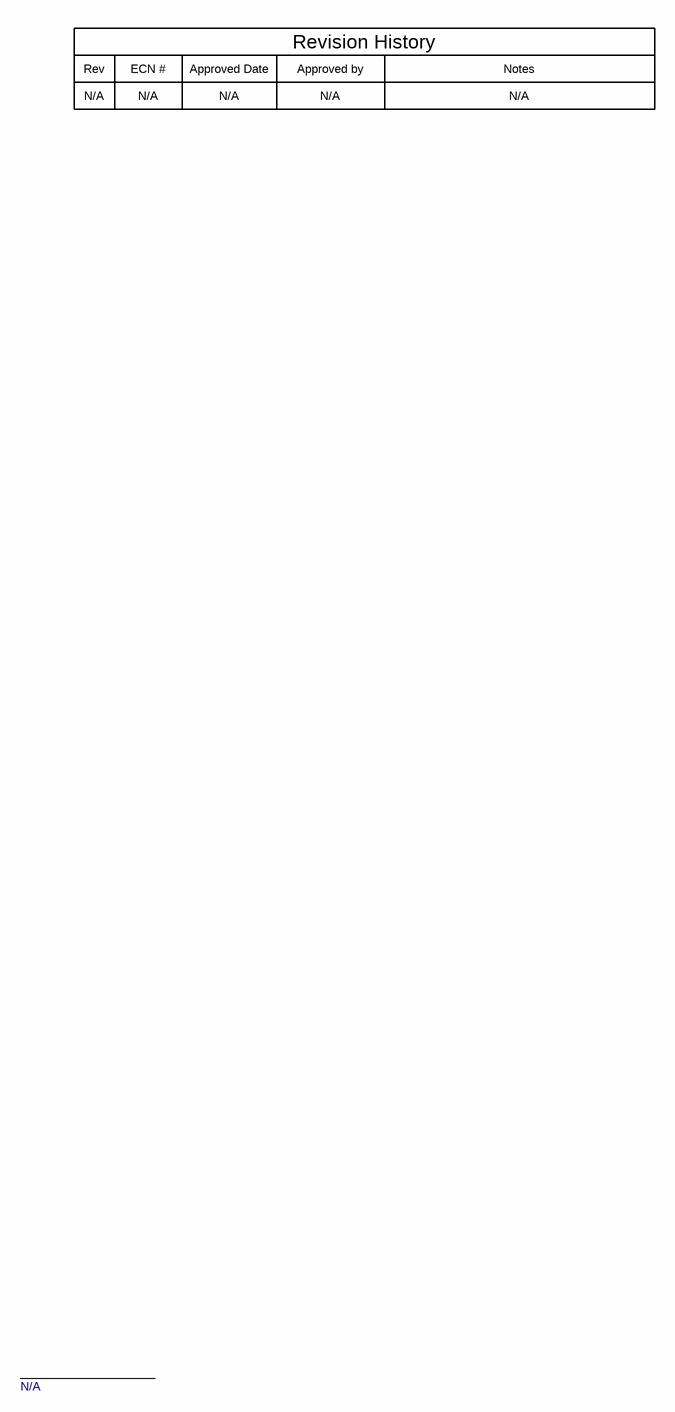
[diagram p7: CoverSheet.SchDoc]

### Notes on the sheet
- Rev
- N/A
- ECN #
- Approved Date
- Approved by
- Revision History
- Notes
